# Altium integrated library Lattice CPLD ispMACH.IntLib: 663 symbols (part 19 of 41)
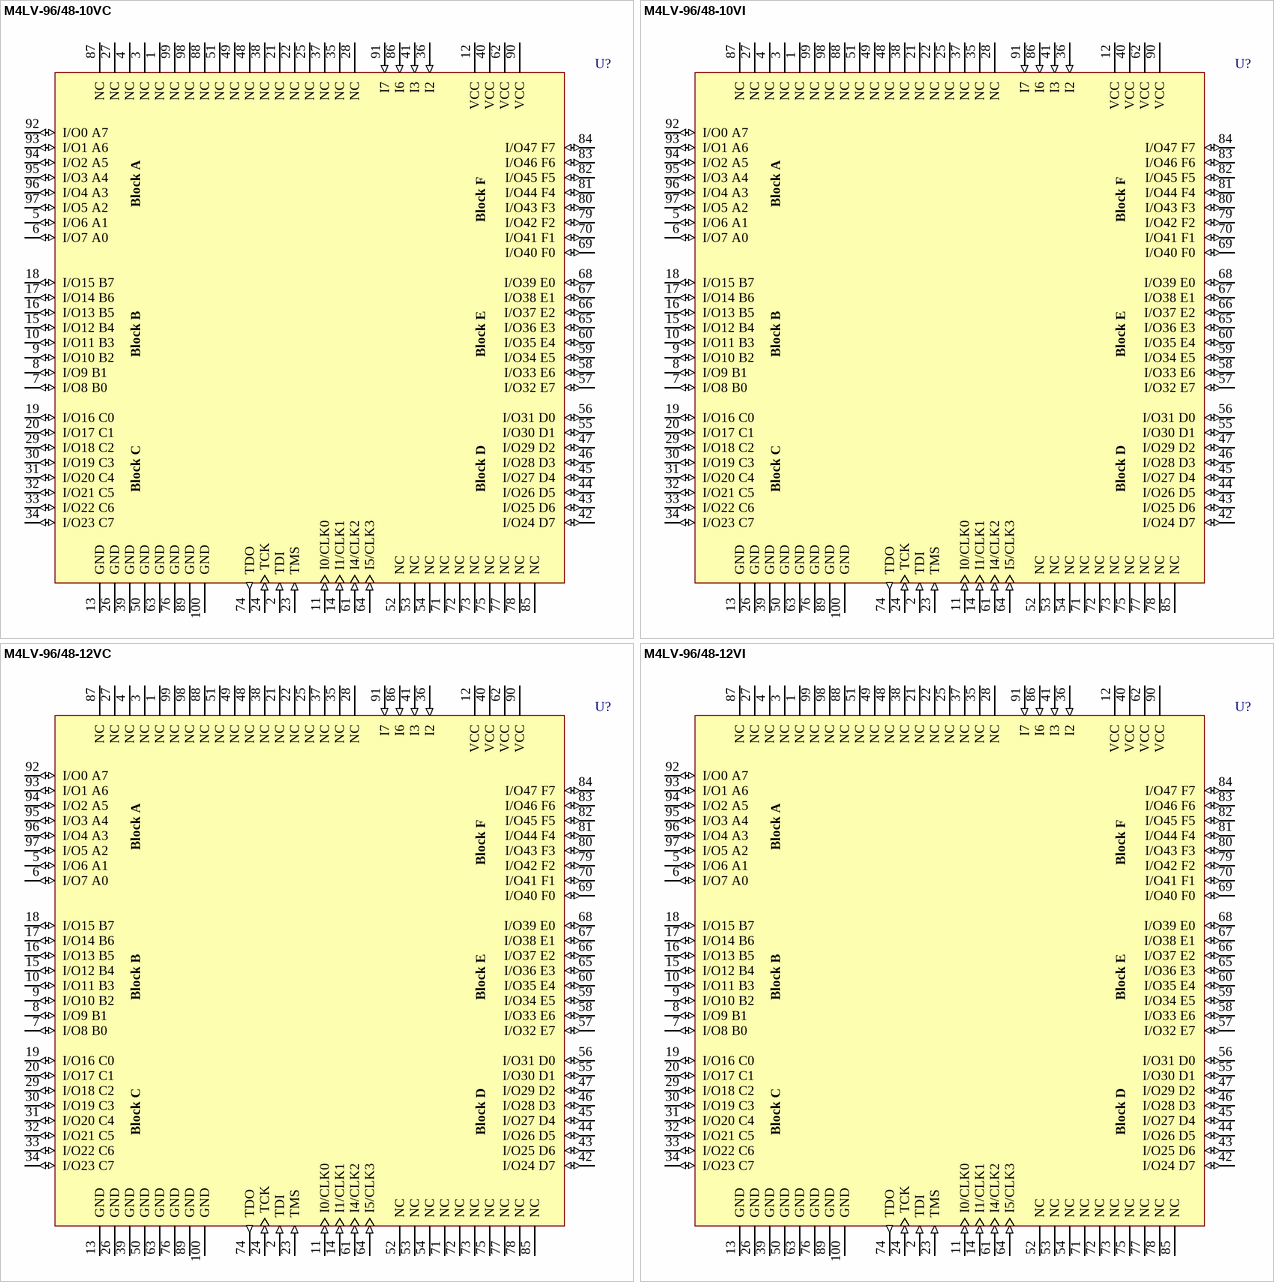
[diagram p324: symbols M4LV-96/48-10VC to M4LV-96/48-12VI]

## M4LV-96/48-10VI
designator U?
High-Performance EE CMOS In-System Programmable Logic
footprint TQFP100_N (Thin QFP, 100-Leads, Body 14x14mm, Pitch 0.5mm, IPC Medium Density)
footprint TQFP100_L (Thin QFP, 100-Leads, Body 14x14mm, Pitch 0.5mm, IPC High Density)
footprint TQFP100_M (Thin QFP, 100-Leads, Body 14x14mm, Pitch 0.5mm, IPC Low Density)
3D model M4LV-TQFP100 (100-Pin Thin Quad Flat Pack (TQFP100))
pins: 1 NC, 2 TDI (in), 3 NC, 4 NC, 5 I/O6 A1 (io), 6 I/O7 A0 (io), 7 I/O8 B0 (io), 8 I/O9 B1 (io), 9 I/O10 B2 (io), 10 I/O11 B3 (io), 11 I0/CLK0 (in), 12 VCC (power), 13 GND (power), 14 I1/CLK1 (in), 15 I/O12 B4 (io), 16 I/O13 B5 (io), 17 I/O14 B6 (io), 18 I/O15 B7 (io), 19 I/O16 C0 (io), 20 I/O17 C1 (io), 21 NC, 22 NC, 23 TMS (in), 24 TCK (in), 25 NC, 26 GND (power), 27 NC, 28 NC, 29 I/O18 C2 (io), 30 I/O19 C3 (io), 31 I/O20 C4 (io), 32 I/O21 C5 (io), 33 I/O22 C6 (io), 34 I/O23 C7 (io), 35 NC, 36 I2 (in), 37 NC, 38 NC, 39 GND (power), 40 VCC (power), 41 I3 (in), 42 I/O24 D7 (io), 43 I/O25 D6 (io), 44 I/O26 D5 (io), 45 I/O27 D4 (io), 46 I/O28 D3 (io), 47 I/O29 D2 (io), 48 NC, 49 NC, 50 GND (power), 51 NC, 52 NC, 53 NC, 54 NC, 55 I/O30 D1 (io), 56 I/O31 D0 (io), 57 I/O32 E7 (io), 58 I/O33 E6 (io), 59 I/O34 E5 (io), 60 I/O35 E4 (io), 61 I4/CLK2 (in), 62 VCC (power), 63 GND (power), 64 I5/CLK3 (in), 65 I/O36 E3 (io), 66 I/O37 E2 (io), 67 I/O38 E1 (io), 68 I/O39 E0 (io), 69 I/O40 F0 (io), 70 I/O41 F1 (io), 71 NC, 72 NC, 73 NC, 74 TDO (out), 75 NC, 76 GND (power), 77 NC, 78 NC, 79 I/O42 F2 (io), 80 I/O43 F3 (io), 81 I/O44 F4 (io), 82 I/O45 F5 (io), 83 I/O46 F6 (io), 84 I/O47 F7 (io), 85 NC, 86 I6 (in), 87 NC, 88 NC, 89 GND (power), 90 VCC (power), 91 I7 (in), 92 I/O0 A7 (io), 93 I/O1 A6 (io), 94 I/O2 A5 (io), 95 I/O3 A4 (io), 96 I/O4 A3 (io), 97 I/O5 A2 (io), 98 NC, 99 NC, 100 GND (power)

## M4LV-96/48-12VC
designator U?
High-Performance EE CMOS In-System Programmable Logic
footprint TQFP100_N (Thin QFP, 100-Leads, Body 14x14mm, Pitch 0.5mm, IPC Medium Density)
footprint TQFP100_L (Thin QFP, 100-Leads, Body 14x14mm, Pitch 0.5mm, IPC High Density)
footprint TQFP100_M (Thin QFP, 100-Leads, Body 14x14mm, Pitch 0.5mm, IPC Low Density)
3D model M4LV-TQFP100 (100-Pin Thin Quad Flat Pack (TQFP100))
pins: 1 NC, 2 TDI (in), 3 NC, 4 NC, 5 I/O6 A1 (io), 6 I/O7 A0 (io), 7 I/O8 B0 (io), 8 I/O9 B1 (io), 9 I/O10 B2 (io), 10 I/O11 B3 (io), 11 I0/CLK0 (in), 12 VCC (power), 13 GND (power), 14 I1/CLK1 (in), 15 I/O12 B4 (io), 16 I/O13 B5 (io), 17 I/O14 B6 (io), 18 I/O15 B7 (io), 19 I/O16 C0 (io), 20 I/O17 C1 (io), 21 NC, 22 NC, 23 TMS (in), 24 TCK (in), 25 NC, 26 GND (power), 27 NC, 28 NC, 29 I/O18 C2 (io), 30 I/O19 C3 (io), 31 I/O20 C4 (io), 32 I/O21 C5 (io), 33 I/O22 C6 (io), 34 I/O23 C7 (io), 35 NC, 36 I2 (in), 37 NC, 38 NC, 39 GND (power), 40 VCC (power), 41 I3 (in), 42 I/O24 D7 (io), 43 I/O25 D6 (io), 44 I/O26 D5 (io), 45 I/O27 D4 (io), 46 I/O28 D3 (io), 47 I/O29 D2 (io), 48 NC, 49 NC, 50 GND (power), 51 NC, 52 NC, 53 NC, 54 NC, 55 I/O30 D1 (io), 56 I/O31 D0 (io), 57 I/O32 E7 (io), 58 I/O33 E6 (io), 59 I/O34 E5 (io), 60 I/O35 E4 (io), 61 I4/CLK2 (in), 62 VCC (power), 63 GND (power), 64 I5/CLK3 (in), 65 I/O36 E3 (io), 66 I/O37 E2 (io), 67 I/O38 E1 (io), 68 I/O39 E0 (io), 69 I/O40 F0 (io), 70 I/O41 F1 (io), 71 NC, 72 NC, 73 NC, 74 TDO (out), 75 NC, 76 GND (power), 77 NC, 78 NC, 79 I/O42 F2 (io), 80 I/O43 F3 (io), 81 I/O44 F4 (io), 82 I/O45 F5 (io), 83 I/O46 F6 (io), 84 I/O47 F7 (io), 85 NC, 86 I6 (in), 87 NC, 88 NC, 89 GND (power), 90 VCC (power), 91 I7 (in), 92 I/O0 A7 (io), 93 I/O1 A6 (io), 94 I/O2 A5 (io), 95 I/O3 A4 (io), 96 I/O4 A3 (io), 97 I/O5 A2 (io), 98 NC, 99 NC, 100 GND (power)

## M4LV-96/48-12VI
designator U?
High-Performance EE CMOS In-System Programmable Logic
footprint TQFP100_N (Thin QFP, 100-Leads, Body 14x14mm, Pitch 0.5mm, IPC Medium Density)
footprint TQFP100_L (Thin QFP, 100-Leads, Body 14x14mm, Pitch 0.5mm, IPC High Density)
footprint TQFP100_M (Thin QFP, 100-Leads, Body 14x14mm, Pitch 0.5mm, IPC Low Density)
3D model M4LV-TQFP100 (100-Pin Thin Quad Flat Pack (TQFP100))
pins: 1 NC, 2 TDI (in), 3 NC, 4 NC, 5 I/O6 A1 (io), 6 I/O7 A0 (io), 7 I/O8 B0 (io), 8 I/O9 B1 (io), 9 I/O10 B2 (io), 10 I/O11 B3 (io), 11 I0/CLK0 (in), 12 VCC (power), 13 GND (power), 14 I1/CLK1 (in), 15 I/O12 B4 (io), 16 I/O13 B5 (io), 17 I/O14 B6 (io), 18 I/O15 B7 (io), 19 I/O16 C0 (io), 20 I/O17 C1 (io), 21 NC, 22 NC, 23 TMS (in), 24 TCK (in), 25 NC, 26 GND (power), 27 NC, 28 NC, 29 I/O18 C2 (io), 30 I/O19 C3 (io), 31 I/O20 C4 (io), 32 I/O21 C5 (io), 33 I/O22 C6 (io), 34 I/O23 C7 (io), 35 NC, 36 I2 (in), 37 NC, 38 NC, 39 GND (power), 40 VCC (power), 41 I3 (in), 42 I/O24 D7 (io), 43 I/O25 D6 (io), 44 I/O26 D5 (io), 45 I/O27 D4 (io), 46 I/O28 D3 (io), 47 I/O29 D2 (io), 48 NC, 49 NC, 50 GND (power), 51 NC, 52 NC, 53 NC, 54 NC, 55 I/O30 D1 (io), 56 I/O31 D0 (io), 57 I/O32 E7 (io), 58 I/O33 E6 (io), 59 I/O34 E5 (io), 60 I/O35 E4 (io), 61 I4/CLK2 (in), 62 VCC (power), 63 GND (power), 64 I5/CLK3 (in), 65 I/O36 E3 (io), 66 I/O37 E2 (io), 67 I/O38 E1 (io), 68 I/O39 E0 (io), 69 I/O40 F0 (io), 70 I/O41 F1 (io), 71 NC, 72 NC, 73 NC, 74 TDO (out), 75 NC, 76 GND (power), 77 NC, 78 NC, 79 I/O42 F2 (io), 80 I/O43 F3 (io), 81 I/O44 F4 (io), 82 I/O45 F5 (io), 83 I/O46 F6 (io), 84 I/O47 F7 (io), 85 NC, 86 I6 (in), 87 NC, 88 NC, 89 GND (power), 90 VCC (power), 91 I7 (in), 92 I/O0 A7 (io), 93 I/O1 A6 (io), 94 I/O2 A5 (io), 95 I/O3 A4 (io), 96 I/O4 A3 (io), 97 I/O5 A2 (io), 98 NC, 99 NC, 100 GND (power)

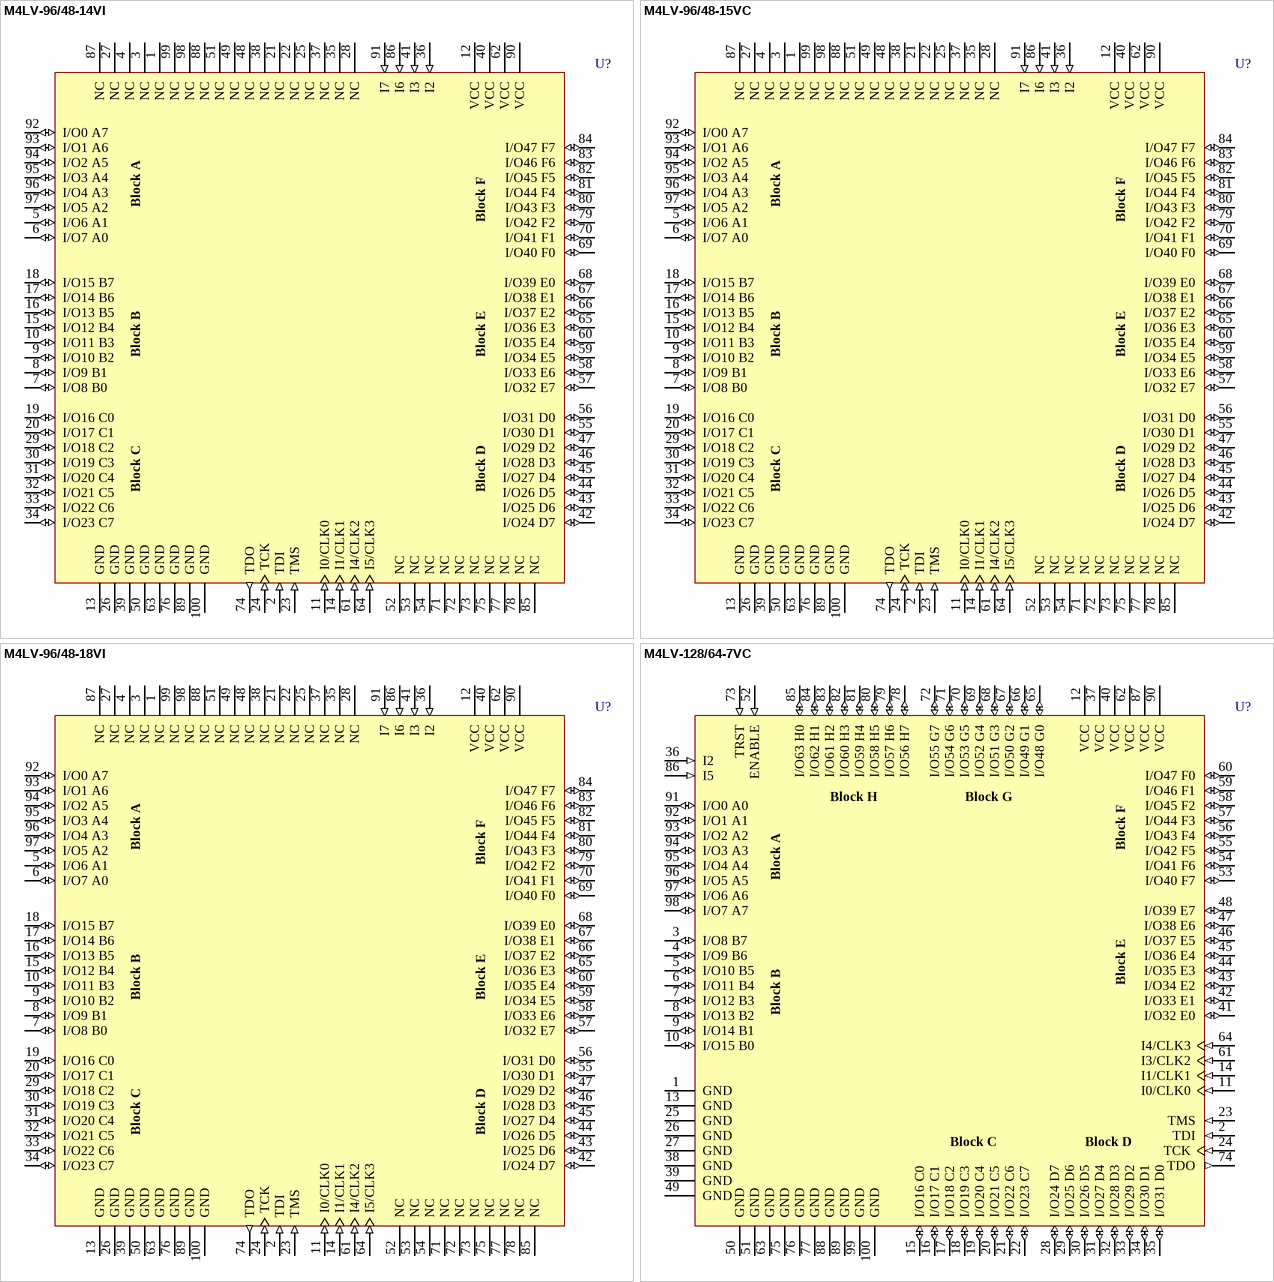
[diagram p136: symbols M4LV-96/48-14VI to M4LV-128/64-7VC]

## M4LV-96/48-14VI
designator U?
High-Performance EE CMOS In-System Programmable Logic
footprint TQFP100_N (Thin QFP, 100-Leads, Body 14x14mm, Pitch 0.5mm, IPC Medium Density)
footprint TQFP100_L (Thin QFP, 100-Leads, Body 14x14mm, Pitch 0.5mm, IPC High Density)
footprint TQFP100_M (Thin QFP, 100-Leads, Body 14x14mm, Pitch 0.5mm, IPC Low Density)
3D model M4LV-TQFP100 (100-Pin Thin Quad Flat Pack (TQFP100))
pins: 1 NC, 2 TDI (in), 3 NC, 4 NC, 5 I/O6 A1 (io), 6 I/O7 A0 (io), 7 I/O8 B0 (io), 8 I/O9 B1 (io), 9 I/O10 B2 (io), 10 I/O11 B3 (io), 11 I0/CLK0 (in), 12 VCC (power), 13 GND (power), 14 I1/CLK1 (in), 15 I/O12 B4 (io), 16 I/O13 B5 (io), 17 I/O14 B6 (io), 18 I/O15 B7 (io), 19 I/O16 C0 (io), 20 I/O17 C1 (io), 21 NC, 22 NC, 23 TMS (in), 24 TCK (in), 25 NC, 26 GND (power), 27 NC, 28 NC, 29 I/O18 C2 (io), 30 I/O19 C3 (io), 31 I/O20 C4 (io), 32 I/O21 C5 (io), 33 I/O22 C6 (io), 34 I/O23 C7 (io), 35 NC, 36 I2 (in), 37 NC, 38 NC, 39 GND (power), 40 VCC (power), 41 I3 (in), 42 I/O24 D7 (io), 43 I/O25 D6 (io), 44 I/O26 D5 (io), 45 I/O27 D4 (io), 46 I/O28 D3 (io), 47 I/O29 D2 (io), 48 NC, 49 NC, 50 GND (power), 51 NC, 52 NC, 53 NC, 54 NC, 55 I/O30 D1 (io), 56 I/O31 D0 (io), 57 I/O32 E7 (io), 58 I/O33 E6 (io), 59 I/O34 E5 (io), 60 I/O35 E4 (io), 61 I4/CLK2 (in), 62 VCC (power), 63 GND (power), 64 I5/CLK3 (in), 65 I/O36 E3 (io), 66 I/O37 E2 (io), 67 I/O38 E1 (io), 68 I/O39 E0 (io), 69 I/O40 F0 (io), 70 I/O41 F1 (io), 71 NC, 72 NC, 73 NC, 74 TDO (out), 75 NC, 76 GND (power), 77 NC, 78 NC, 79 I/O42 F2 (io), 80 I/O43 F3 (io), 81 I/O44 F4 (io), 82 I/O45 F5 (io), 83 I/O46 F6 (io), 84 I/O47 F7 (io), 85 NC, 86 I6 (in), 87 NC, 88 NC, 89 GND (power), 90 VCC (power), 91 I7 (in), 92 I/O0 A7 (io), 93 I/O1 A6 (io), 94 I/O2 A5 (io), 95 I/O3 A4 (io), 96 I/O4 A3 (io), 97 I/O5 A2 (io), 98 NC, 99 NC, 100 GND (power)

## M4LV-96/48-15VC
designator U?
High-Performance EE CMOS In-System Programmable Logic
footprint TQFP100_N (Thin QFP, 100-Leads, Body 14x14mm, Pitch 0.5mm, IPC Medium Density)
footprint TQFP100_L (Thin QFP, 100-Leads, Body 14x14mm, Pitch 0.5mm, IPC High Density)
footprint TQFP100_M (Thin QFP, 100-Leads, Body 14x14mm, Pitch 0.5mm, IPC Low Density)
3D model M4LV-TQFP100 (100-Pin Thin Quad Flat Pack (TQFP100))
pins: 1 NC, 2 TDI (in), 3 NC, 4 NC, 5 I/O6 A1 (io), 6 I/O7 A0 (io), 7 I/O8 B0 (io), 8 I/O9 B1 (io), 9 I/O10 B2 (io), 10 I/O11 B3 (io), 11 I0/CLK0 (in), 12 VCC (power), 13 GND (power), 14 I1/CLK1 (in), 15 I/O12 B4 (io), 16 I/O13 B5 (io), 17 I/O14 B6 (io), 18 I/O15 B7 (io), 19 I/O16 C0 (io), 20 I/O17 C1 (io), 21 NC, 22 NC, 23 TMS (in), 24 TCK (in), 25 NC, 26 GND (power), 27 NC, 28 NC, 29 I/O18 C2 (io), 30 I/O19 C3 (io), 31 I/O20 C4 (io), 32 I/O21 C5 (io), 33 I/O22 C6 (io), 34 I/O23 C7 (io), 35 NC, 36 I2 (in), 37 NC, 38 NC, 39 GND (power), 40 VCC (power), 41 I3 (in), 42 I/O24 D7 (io), 43 I/O25 D6 (io), 44 I/O26 D5 (io), 45 I/O27 D4 (io), 46 I/O28 D3 (io), 47 I/O29 D2 (io), 48 NC, 49 NC, 50 GND (power), 51 NC, 52 NC, 53 NC, 54 NC, 55 I/O30 D1 (io), 56 I/O31 D0 (io), 57 I/O32 E7 (io), 58 I/O33 E6 (io), 59 I/O34 E5 (io), 60 I/O35 E4 (io), 61 I4/CLK2 (in), 62 VCC (power), 63 GND (power), 64 I5/CLK3 (in), 65 I/O36 E3 (io), 66 I/O37 E2 (io), 67 I/O38 E1 (io), 68 I/O39 E0 (io), 69 I/O40 F0 (io), 70 I/O41 F1 (io), 71 NC, 72 NC, 73 NC, 74 TDO (out), 75 NC, 76 GND (power), 77 NC, 78 NC, 79 I/O42 F2 (io), 80 I/O43 F3 (io), 81 I/O44 F4 (io), 82 I/O45 F5 (io), 83 I/O46 F6 (io), 84 I/O47 F7 (io), 85 NC, 86 I6 (in), 87 NC, 88 NC, 89 GND (power), 90 VCC (power), 91 I7 (in), 92 I/O0 A7 (io), 93 I/O1 A6 (io), 94 I/O2 A5 (io), 95 I/O3 A4 (io), 96 I/O4 A3 (io), 97 I/O5 A2 (io), 98 NC, 99 NC, 100 GND (power)

## M4LV-96/48-18VI
designator U?
High-Performance EE CMOS In-System Programmable Logic
footprint TQFP100_N (Thin QFP, 100-Leads, Body 14x14mm, Pitch 0.5mm, IPC Medium Density)
footprint TQFP100_L (Thin QFP, 100-Leads, Body 14x14mm, Pitch 0.5mm, IPC High Density)
footprint TQFP100_M (Thin QFP, 100-Leads, Body 14x14mm, Pitch 0.5mm, IPC Low Density)
3D model M4LV-TQFP100 (100-Pin Thin Quad Flat Pack (TQFP100))
pins: 1 NC, 2 TDI (in), 3 NC, 4 NC, 5 I/O6 A1 (io), 6 I/O7 A0 (io), 7 I/O8 B0 (io), 8 I/O9 B1 (io), 9 I/O10 B2 (io), 10 I/O11 B3 (io), 11 I0/CLK0 (in), 12 VCC (power), 13 GND (power), 14 I1/CLK1 (in), 15 I/O12 B4 (io), 16 I/O13 B5 (io), 17 I/O14 B6 (io), 18 I/O15 B7 (io), 19 I/O16 C0 (io), 20 I/O17 C1 (io), 21 NC, 22 NC, 23 TMS (in), 24 TCK (in), 25 NC, 26 GND (power), 27 NC, 28 NC, 29 I/O18 C2 (io), 30 I/O19 C3 (io), 31 I/O20 C4 (io), 32 I/O21 C5 (io), 33 I/O22 C6 (io), 34 I/O23 C7 (io), 35 NC, 36 I2 (in), 37 NC, 38 NC, 39 GND (power), 40 VCC (power), 41 I3 (in), 42 I/O24 D7 (io), 43 I/O25 D6 (io), 44 I/O26 D5 (io), 45 I/O27 D4 (io), 46 I/O28 D3 (io), 47 I/O29 D2 (io), 48 NC, 49 NC, 50 GND (power), 51 NC, 52 NC, 53 NC, 54 NC, 55 I/O30 D1 (io), 56 I/O31 D0 (io), 57 I/O32 E7 (io), 58 I/O33 E6 (io), 59 I/O34 E5 (io), 60 I/O35 E4 (io), 61 I4/CLK2 (in), 62 VCC (power), 63 GND (power), 64 I5/CLK3 (in), 65 I/O36 E3 (io), 66 I/O37 E2 (io), 67 I/O38 E1 (io), 68 I/O39 E0 (io), 69 I/O40 F0 (io), 70 I/O41 F1 (io), 71 NC, 72 NC, 73 NC, 74 TDO (out), 75 NC, 76 GND (power), 77 NC, 78 NC, 79 I/O42 F2 (io), 80 I/O43 F3 (io), 81 I/O44 F4 (io), 82 I/O45 F5 (io), 83 I/O46 F6 (io), 84 I/O47 F7 (io), 85 NC, 86 I6 (in), 87 NC, 88 NC, 89 GND (power), 90 VCC (power), 91 I7 (in), 92 I/O0 A7 (io), 93 I/O1 A6 (io), 94 I/O2 A5 (io), 95 I/O3 A4 (io), 96 I/O4 A3 (io), 97 I/O5 A2 (io), 98 NC, 99 NC, 100 GND (power)

## M4LV-128/64-7VC
designator U?
High-Performance EE CMOS In-System Programmable Logic
footprint TQFP100_N (Thin QFP, 100-Leads, Body 14x14mm, Pitch 0.5mm, IPC Medium Density)
footprint TQFP100_L (Thin QFP, 100-Leads, Body 14x14mm, Pitch 0.5mm, IPC High Density)
footprint TQFP100_M (Thin QFP, 100-Leads, Body 14x14mm, Pitch 0.5mm, IPC Low Density)
3D model M4LV-TQFP100 (100-Pin Thin Quad Flat Pack (TQFP100))
pins: 1 GND (power), 2 TDI (in), 3 I/O8 B7 (io), 4 I/O9 B6 (io), 5 I/O10 B5 (io), 6 I/O11 B4 (io), 7 I/O12 B3 (io), 8 I/O13 B2 (io), 9 I/O14 B1 (io), 10 I/O15 B0 (io), 11 I0/CLK0 (in), 12 VCC (power), 13 GND (power), 14 I1/CLK1 (in), 15 I/O16 C0 (io), 16 I/O17 C1 (io), 17 I/O18 C2 (io), 18 I/O19 C3 (io), 19 I/O20 C4 (io), 20 I/O21 C5 (io), 21 I/O22 C6 (io), 22 I/O23 C7 (io), 23 TMS (in), 24 TCK (in), 25 GND (power), 26 GND (power), 27 GND (power), 28 I/O24 D7 (io), 29 I/O25 D6 (io), 30 I/O26 D5 (io), 31 I/O27 D4 (io), 32 I/O28 D3 (io), 33 I/O29 D2 (io), 34 I/O30 D1 (io), 35 I/O31 D0 (io), 36 I2 (in), 37 VCC (power), 38 GND (power), 39 GND (power), 40 VCC (power), 41 I/O32 E0 (io), 42 I/O33 E1 (io), 43 I/O34 E2 (io), 44 I/O35 E3 (io), 45 I/O36 E4 (io), 46 I/O37 E5 (io), 47 I/O38 E6 (io), 48 I/O39 E7 (io), 49 GND (power), 50 GND (power), 51 GND (power), 52 ENABLE (in), 53 I/O40 F7 (io), 54 I/O41 F6 (io), 55 I/O42 F5 (io), 56 I/O43 F4 (io), 57 I/O44 F3 (io), 58 I/O45 F2 (io), 59 I/O46 F1 (io), 60 I/O47 F0 (io), 61 I3/CLK2 (in), 62 VCC (power), 63 GND (power), 64 I4/CLK3 (in), 65 I/O48 G0 (io), 66 I/O49 G1 (io), 67 I/O50 G2 (io), 68 I/O51 G3 (io), 69 I/O52 G4 (io), 70 I/O53 G5 (io), 71 I/O54 G6 (io), 72 I/O55 G7 (io), 73 TRST (in), 74 TDO (out), 75 GND (power), 76 GND (power), 77 GND (power), 78 I/O56 H7 (io), 79 I/O57 H6 (io), 80 I/O58 H5 (io), 81 I/O59 H4 (io), 82 I/O60 H3 (io), 83 I/O61 H2 (io), 84 I/O62 H1 (io), 85 I/O63 H0 (io), 86 I5 (in), 87 VCC (power), 88 GND (power), 89 GND (power), 90 VCC (power), 91 I/O0 A0 (io), 92 I/O1 A1 (io), 93 I/O2 A2 (io), 94 I/O3 A3 (io), 95 I/O4 A4 (io), 96 I/O5 A5 (io), 97 I/O6 A6 (io), 98 I/O7 A7 (io), 99 GND (power), 100 GND (power)

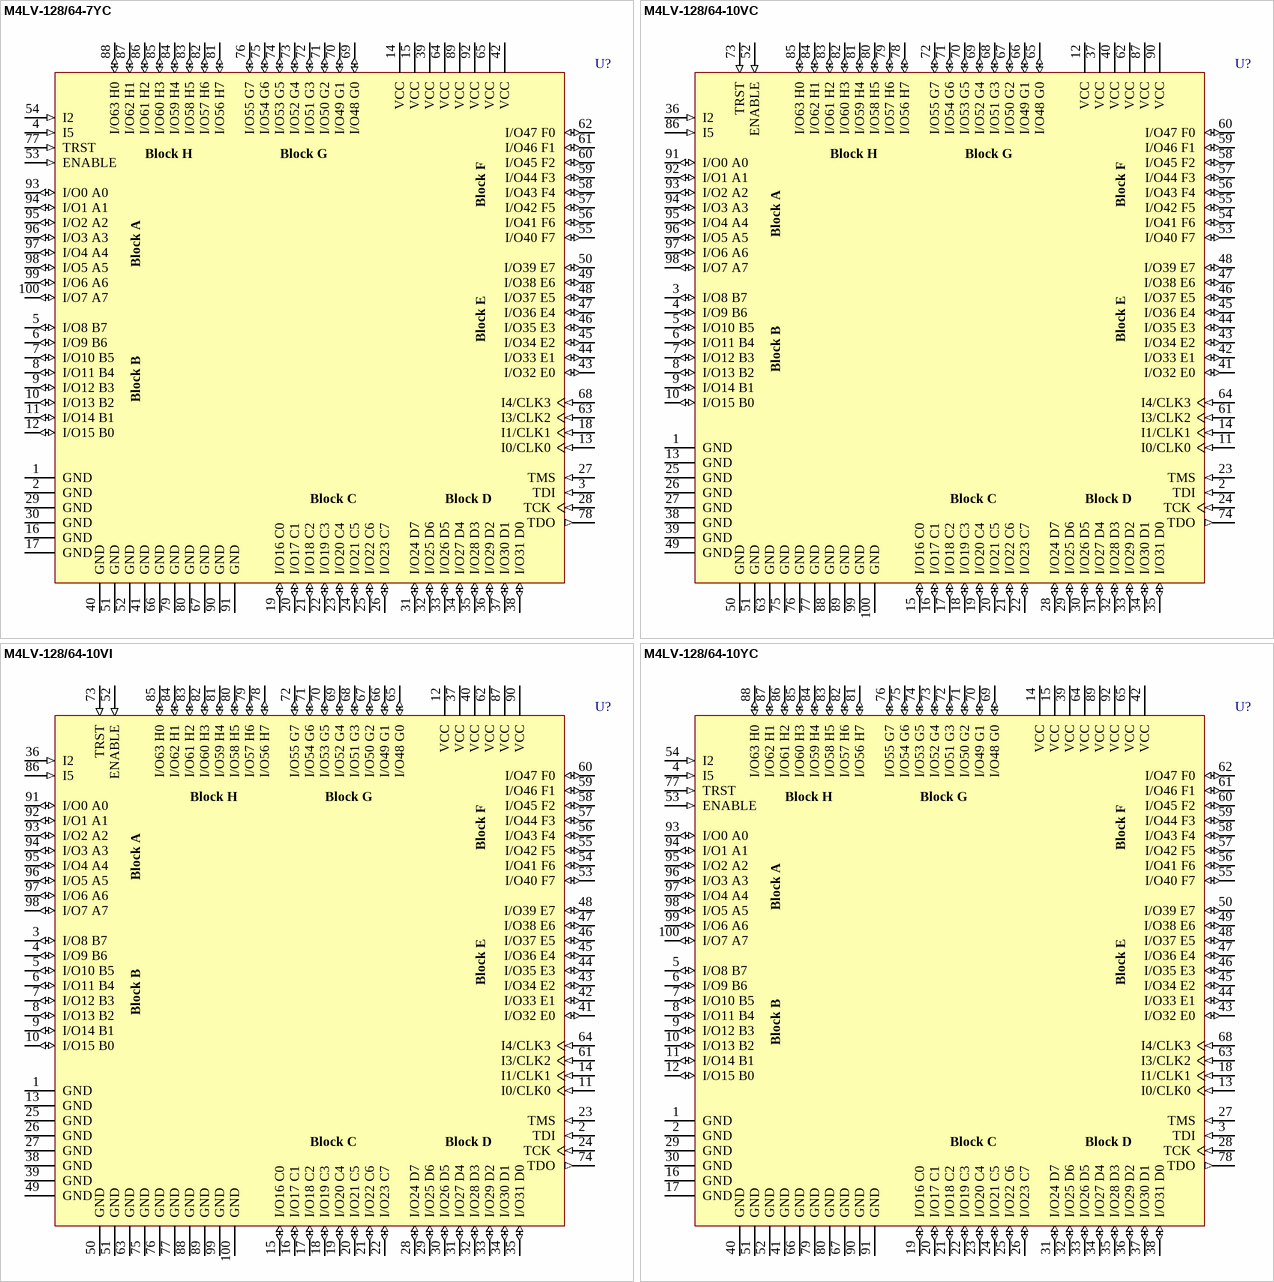
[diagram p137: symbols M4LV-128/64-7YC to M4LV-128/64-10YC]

## M4LV-128/64-7YC
designator U?
High-Performance EE CMOS In-System Programmable Logic
footprint PQFP100_N (QFP, 100-Leads, Body 20x14mm, Pitch 0.65mm, IPC Medium Density)
footprint PQFP100_L (QFP, 100-Leads, Body 20x14mm, Pitch 0.65mm, IPC High Density)
footprint PQFP100_M (QFP, 100-Leads, Body 20x14mm, Pitch 0.65mm, IPC Low Density)
3D model PQFP-100 (100-Pin Quad Flat Pack Rectangular 0.65 mm Pitch)
pins: 1 GND (power), 2 GND (power), 3 TDI (in), 4 I5 (in), 5 I/O8 B7 (io), 6 I/O9 B6 (io), 7 I/O10 B5 (io), 8 I/O11 B4 (io), 9 I/O12 B3 (io), 10 I/O13 B2 (io), 11 I/O14 B1 (io), 12 I/O15 B0 (io), 13 I0/CLK0 (in), 14 VCC (power), 15 VCC (power), 16 GND (power), 17 GND (power), 18 I1/CLK1 (in), 19 I/O16 C0 (io), 20 I/O17 C1 (io), 21 I/O18 C2 (io), 22 I/O19 C3 (io), 23 I/O20 C4 (io), 24 I/O21 C5 (io), 25 I/O22 C6 (io), 26 I/O23 C7 (io), 27 TMS (in), 28 TCK (in), 29 GND (power), 30 GND (power), 31 I/O24 D7 (io), 32 I/O25 D6 (io), 33 I/O26 D5 (io), 34 I/O27 D4 (io), 35 I/O28 D3 (io), 36 I/O29 D2 (io), 37 I/O30 D1 (io), 38 I/O31 D0 (io), 39 VCC (power), 40 GND (power), 41 GND (power), 42 VCC (power), 43 I/O32 E0 (io), 44 I/O33 E1 (io), 45 I/O34 E2 (io), 46 I/O35 E3 (io), 47 I/O36 E4 (io), 48 I/O37 E5 (io), 49 I/O38 E6 (io), 50 I/O39 E7 (io), 51 GND (power), 52 GND (power), 53 ENABLE (in), 54 I2 (in), 55 I/O40 F7 (io), 56 I/O41 F6 (io), 57 I/O42 F5 (io), 58 I/O43 F4 (io), 59 I/O44 F3 (io), 60 I/O45 F2 (io), 61 I/O46 F1 (io), 62 I/O47 F0 (io), 63 I3/CLK2 (in), 64 VCC (power), 65 VCC (power), 66 GND (power), 67 GND (power), 68 I4/CLK3 (in), 69 I/O48 G0 (io), 70 I/O49 G1 (io), 71 I/O50 G2 (io), 72 I/O51 G3 (io), 73 I/O52 G4 (io), 74 I/O53 G5 (io), 75 I/O54 G6 (io), 76 I/O55 G7 (io), 77 TRST (in), 78 TDO (out), 79 GND (power), 80 GND (power), 81 I/O56 H7 (io), 82 I/O57 H6 (io), 83 I/O58 H5 (io), 84 I/O59 H4 (io), 85 I/O60 H3 (io), 86 I/O61 H2 (io), 87 I/O62 H1 (io), 88 I/O63 H0 (io), 89 VCC (power), 90 GND (power), 91 GND (power), 92 VCC (power), 93 I/O0 A0 (io), 94 I/O1 A1 (io), 95 I/O2 A2 (io), 96 I/O3 A3 (io), 97 I/O4 A4 (io), 98 I/O5 A5 (io), 99 I/O6 A6 (io), 100 I/O7 A7 (io)

## M4LV-128/64-10VC
designator U?
High-Performance EE CMOS In-System Programmable Logic
footprint TQFP100_N (Thin QFP, 100-Leads, Body 14x14mm, Pitch 0.5mm, IPC Medium Density)
footprint TQFP100_L (Thin QFP, 100-Leads, Body 14x14mm, Pitch 0.5mm, IPC High Density)
footprint TQFP100_M (Thin QFP, 100-Leads, Body 14x14mm, Pitch 0.5mm, IPC Low Density)
3D model M4LV-TQFP100 (100-Pin Thin Quad Flat Pack (TQFP100))
pins: 1 GND (power), 2 TDI (in), 3 I/O8 B7 (io), 4 I/O9 B6 (io), 5 I/O10 B5 (io), 6 I/O11 B4 (io), 7 I/O12 B3 (io), 8 I/O13 B2 (io), 9 I/O14 B1 (io), 10 I/O15 B0 (io), 11 I0/CLK0 (in), 12 VCC (power), 13 GND (power), 14 I1/CLK1 (in), 15 I/O16 C0 (io), 16 I/O17 C1 (io), 17 I/O18 C2 (io), 18 I/O19 C3 (io), 19 I/O20 C4 (io), 20 I/O21 C5 (io), 21 I/O22 C6 (io), 22 I/O23 C7 (io), 23 TMS (in), 24 TCK (in), 25 GND (power), 26 GND (power), 27 GND (power), 28 I/O24 D7 (io), 29 I/O25 D6 (io), 30 I/O26 D5 (io), 31 I/O27 D4 (io), 32 I/O28 D3 (io), 33 I/O29 D2 (io), 34 I/O30 D1 (io), 35 I/O31 D0 (io), 36 I2 (in), 37 VCC (power), 38 GND (power), 39 GND (power), 40 VCC (power), 41 I/O32 E0 (io), 42 I/O33 E1 (io), 43 I/O34 E2 (io), 44 I/O35 E3 (io), 45 I/O36 E4 (io), 46 I/O37 E5 (io), 47 I/O38 E6 (io), 48 I/O39 E7 (io), 49 GND (power), 50 GND (power), 51 GND (power), 52 ENABLE (in), 53 I/O40 F7 (io), 54 I/O41 F6 (io), 55 I/O42 F5 (io), 56 I/O43 F4 (io), 57 I/O44 F3 (io), 58 I/O45 F2 (io), 59 I/O46 F1 (io), 60 I/O47 F0 (io), 61 I3/CLK2 (in), 62 VCC (power), 63 GND (power), 64 I4/CLK3 (in), 65 I/O48 G0 (io), 66 I/O49 G1 (io), 67 I/O50 G2 (io), 68 I/O51 G3 (io), 69 I/O52 G4 (io), 70 I/O53 G5 (io), 71 I/O54 G6 (io), 72 I/O55 G7 (io), 73 TRST (in), 74 TDO (out), 75 GND (power), 76 GND (power), 77 GND (power), 78 I/O56 H7 (io), 79 I/O57 H6 (io), 80 I/O58 H5 (io), 81 I/O59 H4 (io), 82 I/O60 H3 (io), 83 I/O61 H2 (io), 84 I/O62 H1 (io), 85 I/O63 H0 (io), 86 I5 (in), 87 VCC (power), 88 GND (power), 89 GND (power), 90 VCC (power), 91 I/O0 A0 (io), 92 I/O1 A1 (io), 93 I/O2 A2 (io), 94 I/O3 A3 (io), 95 I/O4 A4 (io), 96 I/O5 A5 (io), 97 I/O6 A6 (io), 98 I/O7 A7 (io), 99 GND (power), 100 GND (power)

## M4LV-128/64-10VI
designator U?
High-Performance EE CMOS In-System Programmable Logic
footprint TQFP100_N (Thin QFP, 100-Leads, Body 14x14mm, Pitch 0.5mm, IPC Medium Density)
footprint TQFP100_L (Thin QFP, 100-Leads, Body 14x14mm, Pitch 0.5mm, IPC High Density)
footprint TQFP100_M (Thin QFP, 100-Leads, Body 14x14mm, Pitch 0.5mm, IPC Low Density)
3D model M4LV-TQFP100 (100-Pin Thin Quad Flat Pack (TQFP100))
pins: 1 GND (power), 2 TDI (in), 3 I/O8 B7 (io), 4 I/O9 B6 (io), 5 I/O10 B5 (io), 6 I/O11 B4 (io), 7 I/O12 B3 (io), 8 I/O13 B2 (io), 9 I/O14 B1 (io), 10 I/O15 B0 (io), 11 I0/CLK0 (in), 12 VCC (power), 13 GND (power), 14 I1/CLK1 (in), 15 I/O16 C0 (io), 16 I/O17 C1 (io), 17 I/O18 C2 (io), 18 I/O19 C3 (io), 19 I/O20 C4 (io), 20 I/O21 C5 (io), 21 I/O22 C6 (io), 22 I/O23 C7 (io), 23 TMS (in), 24 TCK (in), 25 GND (power), 26 GND (power), 27 GND (power), 28 I/O24 D7 (io), 29 I/O25 D6 (io), 30 I/O26 D5 (io), 31 I/O27 D4 (io), 32 I/O28 D3 (io), 33 I/O29 D2 (io), 34 I/O30 D1 (io), 35 I/O31 D0 (io), 36 I2 (in), 37 VCC (power), 38 GND (power), 39 GND (power), 40 VCC (power), 41 I/O32 E0 (io), 42 I/O33 E1 (io), 43 I/O34 E2 (io), 44 I/O35 E3 (io), 45 I/O36 E4 (io), 46 I/O37 E5 (io), 47 I/O38 E6 (io), 48 I/O39 E7 (io), 49 GND (power), 50 GND (power), 51 GND (power), 52 ENABLE (in), 53 I/O40 F7 (io), 54 I/O41 F6 (io), 55 I/O42 F5 (io), 56 I/O43 F4 (io), 57 I/O44 F3 (io), 58 I/O45 F2 (io), 59 I/O46 F1 (io), 60 I/O47 F0 (io), 61 I3/CLK2 (in), 62 VCC (power), 63 GND (power), 64 I4/CLK3 (in), 65 I/O48 G0 (io), 66 I/O49 G1 (io), 67 I/O50 G2 (io), 68 I/O51 G3 (io), 69 I/O52 G4 (io), 70 I/O53 G5 (io), 71 I/O54 G6 (io), 72 I/O55 G7 (io), 73 TRST (in), 74 TDO (out), 75 GND (power), 76 GND (power), 77 GND (power), 78 I/O56 H7 (io), 79 I/O57 H6 (io), 80 I/O58 H5 (io), 81 I/O59 H4 (io), 82 I/O60 H3 (io), 83 I/O61 H2 (io), 84 I/O62 H1 (io), 85 I/O63 H0 (io), 86 I5 (in), 87 VCC (power), 88 GND (power), 89 GND (power), 90 VCC (power), 91 I/O0 A0 (io), 92 I/O1 A1 (io), 93 I/O2 A2 (io), 94 I/O3 A3 (io), 95 I/O4 A4 (io), 96 I/O5 A5 (io), 97 I/O6 A6 (io), 98 I/O7 A7 (io), 99 GND (power), 100 GND (power)

## M4LV-128/64-10YC
designator U?
High-Performance EE CMOS In-System Programmable Logic
footprint PQFP100_N (QFP, 100-Leads, Body 20x14mm, Pitch 0.65mm, IPC Medium Density)
footprint PQFP100_L (QFP, 100-Leads, Body 20x14mm, Pitch 0.65mm, IPC High Density)
footprint PQFP100_M (QFP, 100-Leads, Body 20x14mm, Pitch 0.65mm, IPC Low Density)
3D model PQFP-100 (100-Pin Quad Flat Pack Rectangular 0.65 mm Pitch)
pins: 1 GND (power), 2 GND (power), 3 TDI (in), 4 I5 (in), 5 I/O8 B7 (io), 6 I/O9 B6 (io), 7 I/O10 B5 (io), 8 I/O11 B4 (io), 9 I/O12 B3 (io), 10 I/O13 B2 (io), 11 I/O14 B1 (io), 12 I/O15 B0 (io), 13 I0/CLK0 (in), 14 VCC (power), 15 VCC (power), 16 GND (power), 17 GND (power), 18 I1/CLK1 (in), 19 I/O16 C0 (io), 20 I/O17 C1 (io), 21 I/O18 C2 (io), 22 I/O19 C3 (io), 23 I/O20 C4 (io), 24 I/O21 C5 (io), 25 I/O22 C6 (io), 26 I/O23 C7 (io), 27 TMS (in), 28 TCK (in), 29 GND (power), 30 GND (power), 31 I/O24 D7 (io), 32 I/O25 D6 (io), 33 I/O26 D5 (io), 34 I/O27 D4 (io), 35 I/O28 D3 (io), 36 I/O29 D2 (io), 37 I/O30 D1 (io), 38 I/O31 D0 (io), 39 VCC (power), 40 GND (power), 41 GND (power), 42 VCC (power), 43 I/O32 E0 (io), 44 I/O33 E1 (io), 45 I/O34 E2 (io), 46 I/O35 E3 (io), 47 I/O36 E4 (io), 48 I/O37 E5 (io), 49 I/O38 E6 (io), 50 I/O39 E7 (io), 51 GND (power), 52 GND (power), 53 ENABLE (in), 54 I2 (in), 55 I/O40 F7 (io), 56 I/O41 F6 (io), 57 I/O42 F5 (io), 58 I/O43 F4 (io), 59 I/O44 F3 (io), 60 I/O45 F2 (io), 61 I/O46 F1 (io), 62 I/O47 F0 (io), 63 I3/CLK2 (in), 64 VCC (power), 65 VCC (power), 66 GND (power), 67 GND (power), 68 I4/CLK3 (in), 69 I/O48 G0 (io), 70 I/O49 G1 (io), 71 I/O50 G2 (io), 72 I/O51 G3 (io), 73 I/O52 G4 (io), 74 I/O53 G5 (io), 75 I/O54 G6 (io), 76 I/O55 G7 (io), 77 TRST (in), 78 TDO (out), 79 GND (power), 80 GND (power), 81 I/O56 H7 (io), 82 I/O57 H6 (io), 83 I/O58 H5 (io), 84 I/O59 H4 (io), 85 I/O60 H3 (io), 86 I/O61 H2 (io), 87 I/O62 H1 (io), 88 I/O63 H0 (io), 89 VCC (power), 90 GND (power), 91 GND (power), 92 VCC (power), 93 I/O0 A0 (io), 94 I/O1 A1 (io), 95 I/O2 A2 (io), 96 I/O3 A3 (io), 97 I/O4 A4 (io), 98 I/O5 A5 (io), 99 I/O6 A6 (io), 100 I/O7 A7 (io)

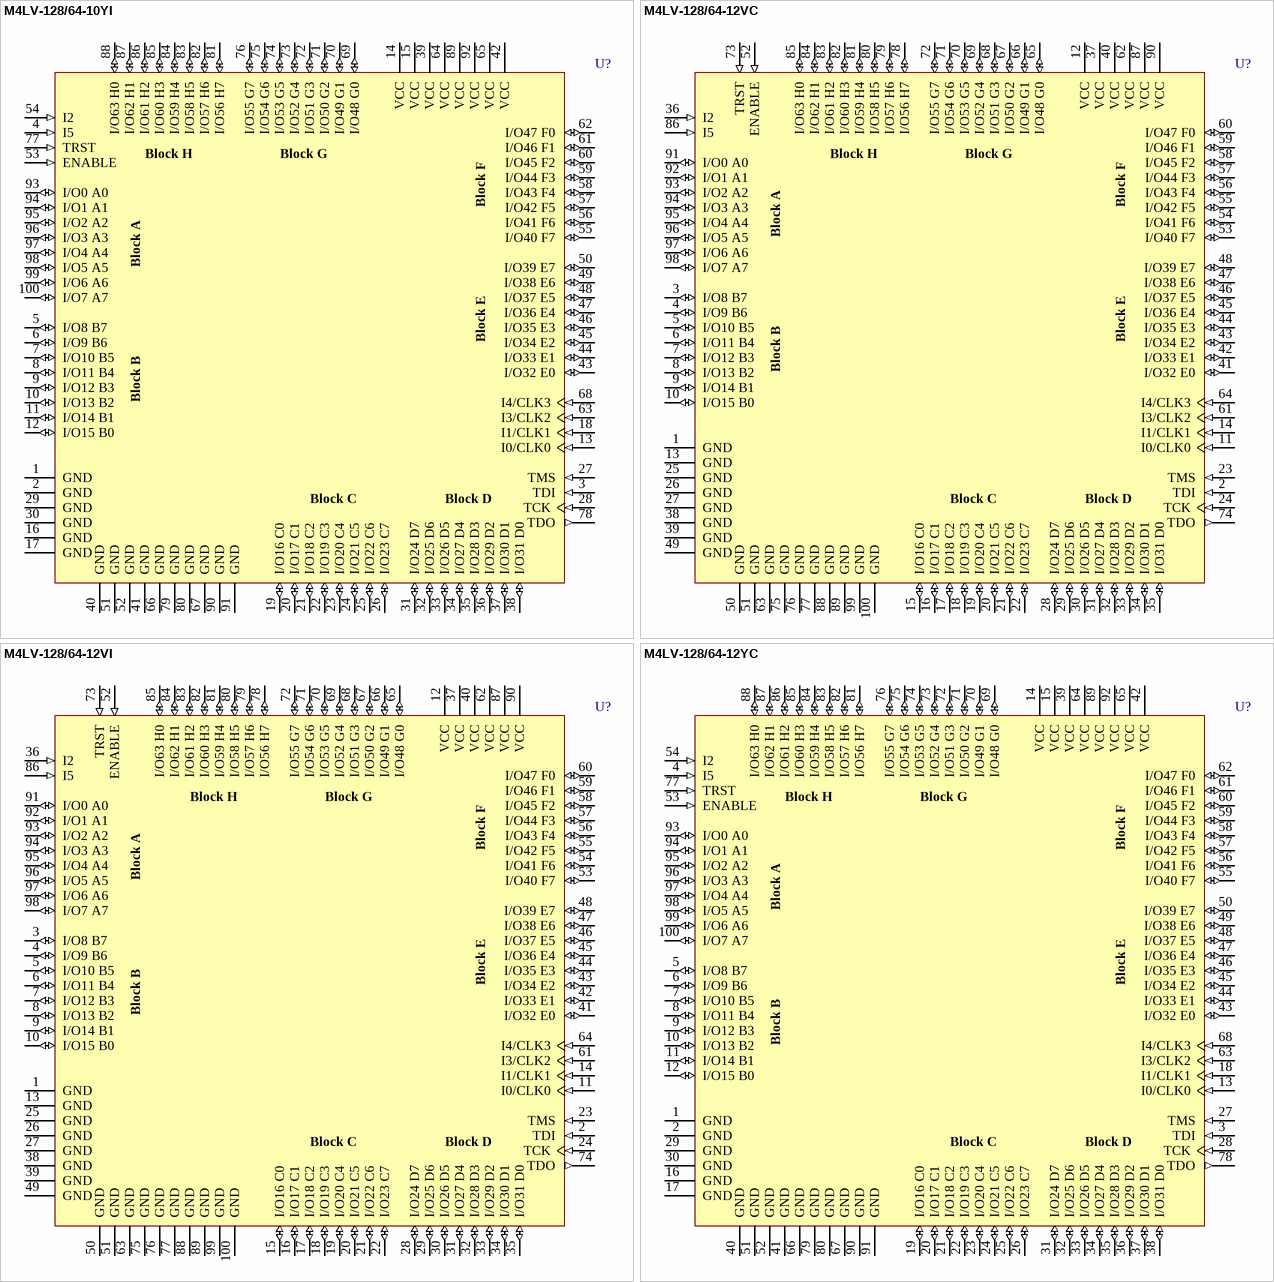
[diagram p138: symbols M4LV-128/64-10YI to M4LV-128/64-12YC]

## M4LV-128/64-10YI
designator U?
High-Performance EE CMOS In-System Programmable Logic
footprint PQFP100_N (QFP, 100-Leads, Body 20x14mm, Pitch 0.65mm, IPC Medium Density)
footprint PQFP100_L (QFP, 100-Leads, Body 20x14mm, Pitch 0.65mm, IPC High Density)
footprint PQFP100_M (QFP, 100-Leads, Body 20x14mm, Pitch 0.65mm, IPC Low Density)
3D model PQFP-100 (100-Pin Quad Flat Pack Rectangular 0.65 mm Pitch)
pins: 1 GND (power), 2 GND (power), 3 TDI (in), 4 I5 (in), 5 I/O8 B7 (io), 6 I/O9 B6 (io), 7 I/O10 B5 (io), 8 I/O11 B4 (io), 9 I/O12 B3 (io), 10 I/O13 B2 (io), 11 I/O14 B1 (io), 12 I/O15 B0 (io), 13 I0/CLK0 (in), 14 VCC (power), 15 VCC (power), 16 GND (power), 17 GND (power), 18 I1/CLK1 (in), 19 I/O16 C0 (io), 20 I/O17 C1 (io), 21 I/O18 C2 (io), 22 I/O19 C3 (io), 23 I/O20 C4 (io), 24 I/O21 C5 (io), 25 I/O22 C6 (io), 26 I/O23 C7 (io), 27 TMS (in), 28 TCK (in), 29 GND (power), 30 GND (power), 31 I/O24 D7 (io), 32 I/O25 D6 (io), 33 I/O26 D5 (io), 34 I/O27 D4 (io), 35 I/O28 D3 (io), 36 I/O29 D2 (io), 37 I/O30 D1 (io), 38 I/O31 D0 (io), 39 VCC (power), 40 GND (power), 41 GND (power), 42 VCC (power), 43 I/O32 E0 (io), 44 I/O33 E1 (io), 45 I/O34 E2 (io), 46 I/O35 E3 (io), 47 I/O36 E4 (io), 48 I/O37 E5 (io), 49 I/O38 E6 (io), 50 I/O39 E7 (io), 51 GND (power), 52 GND (power), 53 ENABLE (in), 54 I2 (in), 55 I/O40 F7 (io), 56 I/O41 F6 (io), 57 I/O42 F5 (io), 58 I/O43 F4 (io), 59 I/O44 F3 (io), 60 I/O45 F2 (io), 61 I/O46 F1 (io), 62 I/O47 F0 (io), 63 I3/CLK2 (in), 64 VCC (power), 65 VCC (power), 66 GND (power), 67 GND (power), 68 I4/CLK3 (in), 69 I/O48 G0 (io), 70 I/O49 G1 (io), 71 I/O50 G2 (io), 72 I/O51 G3 (io), 73 I/O52 G4 (io), 74 I/O53 G5 (io), 75 I/O54 G6 (io), 76 I/O55 G7 (io), 77 TRST (in), 78 TDO (out), 79 GND (power), 80 GND (power), 81 I/O56 H7 (io), 82 I/O57 H6 (io), 83 I/O58 H5 (io), 84 I/O59 H4 (io), 85 I/O60 H3 (io), 86 I/O61 H2 (io), 87 I/O62 H1 (io), 88 I/O63 H0 (io), 89 VCC (power), 90 GND (power), 91 GND (power), 92 VCC (power), 93 I/O0 A0 (io), 94 I/O1 A1 (io), 95 I/O2 A2 (io), 96 I/O3 A3 (io), 97 I/O4 A4 (io), 98 I/O5 A5 (io), 99 I/O6 A6 (io), 100 I/O7 A7 (io)

## M4LV-128/64-12VC
designator U?
High-Performance EE CMOS In-System Programmable Logic
footprint TQFP100_N (Thin QFP, 100-Leads, Body 14x14mm, Pitch 0.5mm, IPC Medium Density)
footprint TQFP100_L (Thin QFP, 100-Leads, Body 14x14mm, Pitch 0.5mm, IPC High Density)
footprint TQFP100_M (Thin QFP, 100-Leads, Body 14x14mm, Pitch 0.5mm, IPC Low Density)
3D model M4LV-TQFP100 (100-Pin Thin Quad Flat Pack (TQFP100))
pins: 1 GND (power), 2 TDI (in), 3 I/O8 B7 (io), 4 I/O9 B6 (io), 5 I/O10 B5 (io), 6 I/O11 B4 (io), 7 I/O12 B3 (io), 8 I/O13 B2 (io), 9 I/O14 B1 (io), 10 I/O15 B0 (io), 11 I0/CLK0 (in), 12 VCC (power), 13 GND (power), 14 I1/CLK1 (in), 15 I/O16 C0 (io), 16 I/O17 C1 (io), 17 I/O18 C2 (io), 18 I/O19 C3 (io), 19 I/O20 C4 (io), 20 I/O21 C5 (io), 21 I/O22 C6 (io), 22 I/O23 C7 (io), 23 TMS (in), 24 TCK (in), 25 GND (power), 26 GND (power), 27 GND (power), 28 I/O24 D7 (io), 29 I/O25 D6 (io), 30 I/O26 D5 (io), 31 I/O27 D4 (io), 32 I/O28 D3 (io), 33 I/O29 D2 (io), 34 I/O30 D1 (io), 35 I/O31 D0 (io), 36 I2 (in), 37 VCC (power), 38 GND (power), 39 GND (power), 40 VCC (power), 41 I/O32 E0 (io), 42 I/O33 E1 (io), 43 I/O34 E2 (io), 44 I/O35 E3 (io), 45 I/O36 E4 (io), 46 I/O37 E5 (io), 47 I/O38 E6 (io), 48 I/O39 E7 (io), 49 GND (power), 50 GND (power), 51 GND (power), 52 ENABLE (in), 53 I/O40 F7 (io), 54 I/O41 F6 (io), 55 I/O42 F5 (io), 56 I/O43 F4 (io), 57 I/O44 F3 (io), 58 I/O45 F2 (io), 59 I/O46 F1 (io), 60 I/O47 F0 (io), 61 I3/CLK2 (in), 62 VCC (power), 63 GND (power), 64 I4/CLK3 (in), 65 I/O48 G0 (io), 66 I/O49 G1 (io), 67 I/O50 G2 (io), 68 I/O51 G3 (io), 69 I/O52 G4 (io), 70 I/O53 G5 (io), 71 I/O54 G6 (io), 72 I/O55 G7 (io), 73 TRST (in), 74 TDO (out), 75 GND (power), 76 GND (power), 77 GND (power), 78 I/O56 H7 (io), 79 I/O57 H6 (io), 80 I/O58 H5 (io), 81 I/O59 H4 (io), 82 I/O60 H3 (io), 83 I/O61 H2 (io), 84 I/O62 H1 (io), 85 I/O63 H0 (io), 86 I5 (in), 87 VCC (power), 88 GND (power), 89 GND (power), 90 VCC (power), 91 I/O0 A0 (io), 92 I/O1 A1 (io), 93 I/O2 A2 (io), 94 I/O3 A3 (io), 95 I/O4 A4 (io), 96 I/O5 A5 (io), 97 I/O6 A6 (io), 98 I/O7 A7 (io), 99 GND (power), 100 GND (power)

## M4LV-128/64-12VI
designator U?
High-Performance EE CMOS In-System Programmable Logic
footprint TQFP100_N (Thin QFP, 100-Leads, Body 14x14mm, Pitch 0.5mm, IPC Medium Density)
footprint TQFP100_L (Thin QFP, 100-Leads, Body 14x14mm, Pitch 0.5mm, IPC High Density)
footprint TQFP100_M (Thin QFP, 100-Leads, Body 14x14mm, Pitch 0.5mm, IPC Low Density)
3D model M4LV-TQFP100 (100-Pin Thin Quad Flat Pack (TQFP100))
pins: 1 GND (power), 2 TDI (in), 3 I/O8 B7 (io), 4 I/O9 B6 (io), 5 I/O10 B5 (io), 6 I/O11 B4 (io), 7 I/O12 B3 (io), 8 I/O13 B2 (io), 9 I/O14 B1 (io), 10 I/O15 B0 (io), 11 I0/CLK0 (in), 12 VCC (power), 13 GND (power), 14 I1/CLK1 (in), 15 I/O16 C0 (io), 16 I/O17 C1 (io), 17 I/O18 C2 (io), 18 I/O19 C3 (io), 19 I/O20 C4 (io), 20 I/O21 C5 (io), 21 I/O22 C6 (io), 22 I/O23 C7 (io), 23 TMS (in), 24 TCK (in), 25 GND (power), 26 GND (power), 27 GND (power), 28 I/O24 D7 (io), 29 I/O25 D6 (io), 30 I/O26 D5 (io), 31 I/O27 D4 (io), 32 I/O28 D3 (io), 33 I/O29 D2 (io), 34 I/O30 D1 (io), 35 I/O31 D0 (io), 36 I2 (in), 37 VCC (power), 38 GND (power), 39 GND (power), 40 VCC (power), 41 I/O32 E0 (io), 42 I/O33 E1 (io), 43 I/O34 E2 (io), 44 I/O35 E3 (io), 45 I/O36 E4 (io), 46 I/O37 E5 (io), 47 I/O38 E6 (io), 48 I/O39 E7 (io), 49 GND (power), 50 GND (power), 51 GND (power), 52 ENABLE (in), 53 I/O40 F7 (io), 54 I/O41 F6 (io), 55 I/O42 F5 (io), 56 I/O43 F4 (io), 57 I/O44 F3 (io), 58 I/O45 F2 (io), 59 I/O46 F1 (io), 60 I/O47 F0 (io), 61 I3/CLK2 (in), 62 VCC (power), 63 GND (power), 64 I4/CLK3 (in), 65 I/O48 G0 (io), 66 I/O49 G1 (io), 67 I/O50 G2 (io), 68 I/O51 G3 (io), 69 I/O52 G4 (io), 70 I/O53 G5 (io), 71 I/O54 G6 (io), 72 I/O55 G7 (io), 73 TRST (in), 74 TDO (out), 75 GND (power), 76 GND (power), 77 GND (power), 78 I/O56 H7 (io), 79 I/O57 H6 (io), 80 I/O58 H5 (io), 81 I/O59 H4 (io), 82 I/O60 H3 (io), 83 I/O61 H2 (io), 84 I/O62 H1 (io), 85 I/O63 H0 (io), 86 I5 (in), 87 VCC (power), 88 GND (power), 89 GND (power), 90 VCC (power), 91 I/O0 A0 (io), 92 I/O1 A1 (io), 93 I/O2 A2 (io), 94 I/O3 A3 (io), 95 I/O4 A4 (io), 96 I/O5 A5 (io), 97 I/O6 A6 (io), 98 I/O7 A7 (io), 99 GND (power), 100 GND (power)

## M4LV-128/64-12YC
designator U?
High-Performance EE CMOS In-System Programmable Logic
footprint PQFP100_N (QFP, 100-Leads, Body 20x14mm, Pitch 0.65mm, IPC Medium Density)
footprint PQFP100_L (QFP, 100-Leads, Body 20x14mm, Pitch 0.65mm, IPC High Density)
footprint PQFP100_M (QFP, 100-Leads, Body 20x14mm, Pitch 0.65mm, IPC Low Density)
3D model PQFP-100 (100-Pin Quad Flat Pack Rectangular 0.65 mm Pitch)
pins: 1 GND (power), 2 GND (power), 3 TDI (in), 4 I5 (in), 5 I/O8 B7 (io), 6 I/O9 B6 (io), 7 I/O10 B5 (io), 8 I/O11 B4 (io), 9 I/O12 B3 (io), 10 I/O13 B2 (io), 11 I/O14 B1 (io), 12 I/O15 B0 (io), 13 I0/CLK0 (in), 14 VCC (power), 15 VCC (power), 16 GND (power), 17 GND (power), 18 I1/CLK1 (in), 19 I/O16 C0 (io), 20 I/O17 C1 (io), 21 I/O18 C2 (io), 22 I/O19 C3 (io), 23 I/O20 C4 (io), 24 I/O21 C5 (io), 25 I/O22 C6 (io), 26 I/O23 C7 (io), 27 TMS (in), 28 TCK (in), 29 GND (power), 30 GND (power), 31 I/O24 D7 (io), 32 I/O25 D6 (io), 33 I/O26 D5 (io), 34 I/O27 D4 (io), 35 I/O28 D3 (io), 36 I/O29 D2 (io), 37 I/O30 D1 (io), 38 I/O31 D0 (io), 39 VCC (power), 40 GND (power), 41 GND (power), 42 VCC (power), 43 I/O32 E0 (io), 44 I/O33 E1 (io), 45 I/O34 E2 (io), 46 I/O35 E3 (io), 47 I/O36 E4 (io), 48 I/O37 E5 (io), 49 I/O38 E6 (io), 50 I/O39 E7 (io), 51 GND (power), 52 GND (power), 53 ENABLE (in), 54 I2 (in), 55 I/O40 F7 (io), 56 I/O41 F6 (io), 57 I/O42 F5 (io), 58 I/O43 F4 (io), 59 I/O44 F3 (io), 60 I/O45 F2 (io), 61 I/O46 F1 (io), 62 I/O47 F0 (io), 63 I3/CLK2 (in), 64 VCC (power), 65 VCC (power), 66 GND (power), 67 GND (power), 68 I4/CLK3 (in), 69 I/O48 G0 (io), 70 I/O49 G1 (io), 71 I/O50 G2 (io), 72 I/O51 G3 (io), 73 I/O52 G4 (io), 74 I/O53 G5 (io), 75 I/O54 G6 (io), 76 I/O55 G7 (io), 77 TRST (in), 78 TDO (out), 79 GND (power), 80 GND (power), 81 I/O56 H7 (io), 82 I/O57 H6 (io), 83 I/O58 H5 (io), 84 I/O59 H4 (io), 85 I/O60 H3 (io), 86 I/O61 H2 (io), 87 I/O62 H1 (io), 88 I/O63 H0 (io), 89 VCC (power), 90 GND (power), 91 GND (power), 92 VCC (power), 93 I/O0 A0 (io), 94 I/O1 A1 (io), 95 I/O2 A2 (io), 96 I/O3 A3 (io), 97 I/O4 A4 (io), 98 I/O5 A5 (io), 99 I/O6 A6 (io), 100 I/O7 A7 (io)

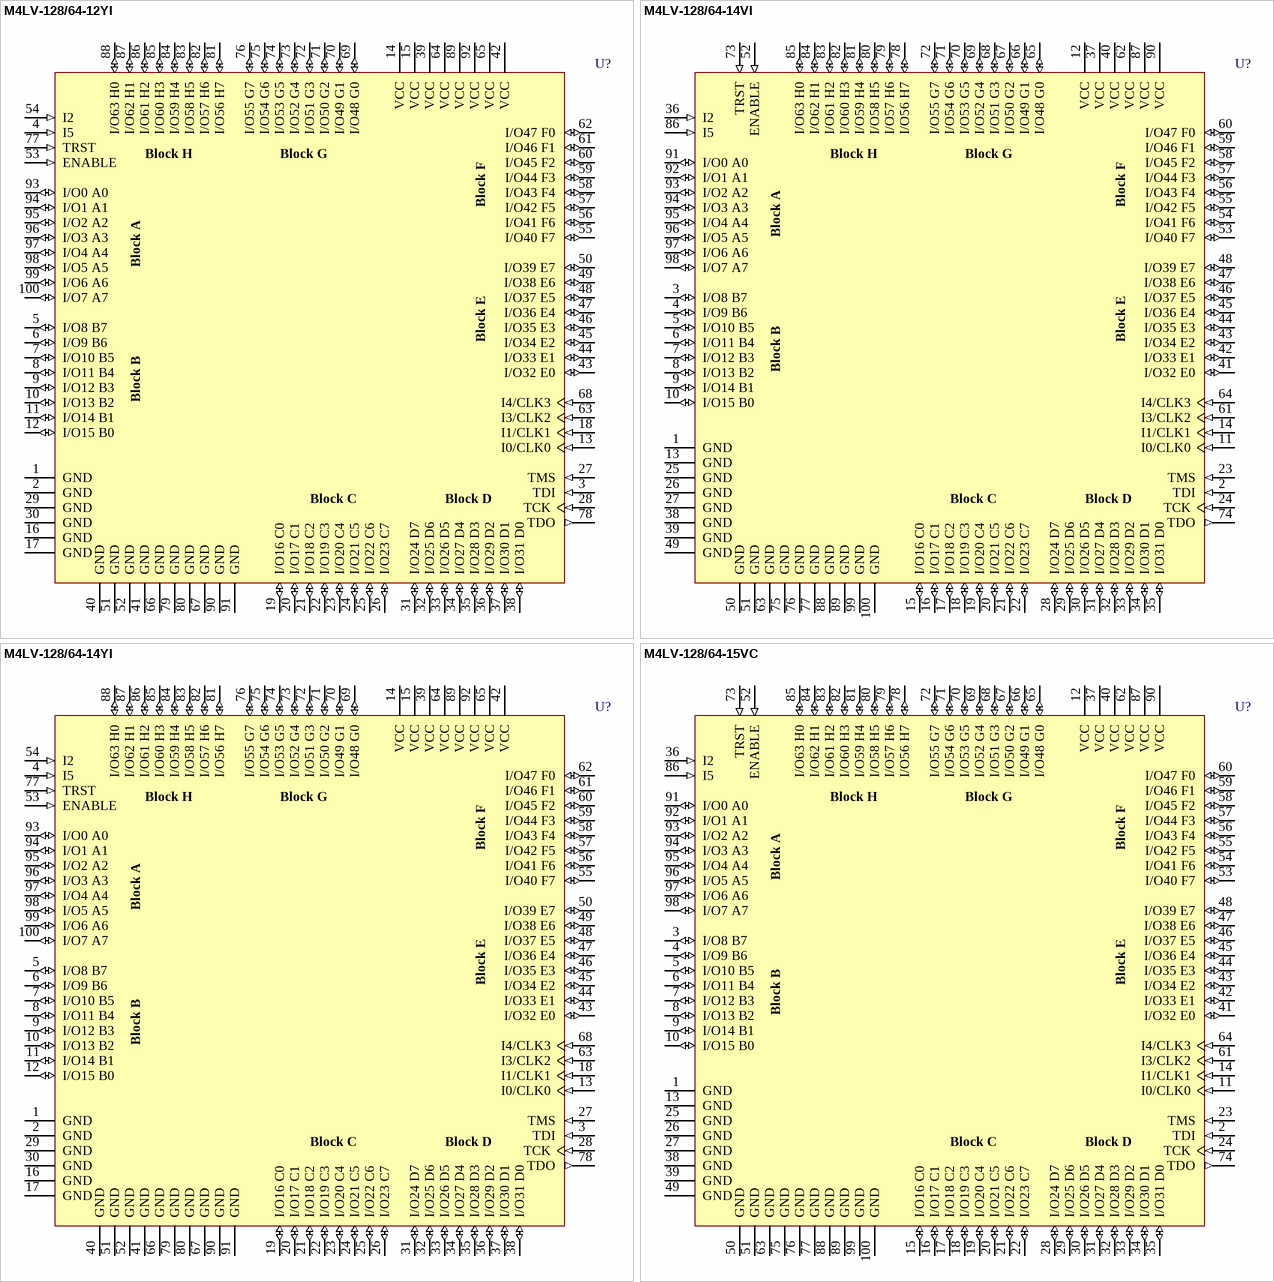
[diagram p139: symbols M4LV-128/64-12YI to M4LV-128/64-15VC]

## M4LV-128/64-12YI
designator U?
High-Performance EE CMOS In-System Programmable Logic
footprint PQFP100_N (QFP, 100-Leads, Body 20x14mm, Pitch 0.65mm, IPC Medium Density)
footprint PQFP100_L (QFP, 100-Leads, Body 20x14mm, Pitch 0.65mm, IPC High Density)
footprint PQFP100_M (QFP, 100-Leads, Body 20x14mm, Pitch 0.65mm, IPC Low Density)
3D model PQFP-100 (100-Pin Quad Flat Pack Rectangular 0.65 mm Pitch)
pins: 1 GND (power), 2 GND (power), 3 TDI (in), 4 I5 (in), 5 I/O8 B7 (io), 6 I/O9 B6 (io), 7 I/O10 B5 (io), 8 I/O11 B4 (io), 9 I/O12 B3 (io), 10 I/O13 B2 (io), 11 I/O14 B1 (io), 12 I/O15 B0 (io), 13 I0/CLK0 (in), 14 VCC (power), 15 VCC (power), 16 GND (power), 17 GND (power), 18 I1/CLK1 (in), 19 I/O16 C0 (io), 20 I/O17 C1 (io), 21 I/O18 C2 (io), 22 I/O19 C3 (io), 23 I/O20 C4 (io), 24 I/O21 C5 (io), 25 I/O22 C6 (io), 26 I/O23 C7 (io), 27 TMS (in), 28 TCK (in), 29 GND (power), 30 GND (power), 31 I/O24 D7 (io), 32 I/O25 D6 (io), 33 I/O26 D5 (io), 34 I/O27 D4 (io), 35 I/O28 D3 (io), 36 I/O29 D2 (io), 37 I/O30 D1 (io), 38 I/O31 D0 (io), 39 VCC (power), 40 GND (power), 41 GND (power), 42 VCC (power), 43 I/O32 E0 (io), 44 I/O33 E1 (io), 45 I/O34 E2 (io), 46 I/O35 E3 (io), 47 I/O36 E4 (io), 48 I/O37 E5 (io), 49 I/O38 E6 (io), 50 I/O39 E7 (io), 51 GND (power), 52 GND (power), 53 ENABLE (in), 54 I2 (in), 55 I/O40 F7 (io), 56 I/O41 F6 (io), 57 I/O42 F5 (io), 58 I/O43 F4 (io), 59 I/O44 F3 (io), 60 I/O45 F2 (io), 61 I/O46 F1 (io), 62 I/O47 F0 (io), 63 I3/CLK2 (in), 64 VCC (power), 65 VCC (power), 66 GND (power), 67 GND (power), 68 I4/CLK3 (in), 69 I/O48 G0 (io), 70 I/O49 G1 (io), 71 I/O50 G2 (io), 72 I/O51 G3 (io), 73 I/O52 G4 (io), 74 I/O53 G5 (io), 75 I/O54 G6 (io), 76 I/O55 G7 (io), 77 TRST (in), 78 TDO (out), 79 GND (power), 80 GND (power), 81 I/O56 H7 (io), 82 I/O57 H6 (io), 83 I/O58 H5 (io), 84 I/O59 H4 (io), 85 I/O60 H3 (io), 86 I/O61 H2 (io), 87 I/O62 H1 (io), 88 I/O63 H0 (io), 89 VCC (power), 90 GND (power), 91 GND (power), 92 VCC (power), 93 I/O0 A0 (io), 94 I/O1 A1 (io), 95 I/O2 A2 (io), 96 I/O3 A3 (io), 97 I/O4 A4 (io), 98 I/O5 A5 (io), 99 I/O6 A6 (io), 100 I/O7 A7 (io)

## M4LV-128/64-14VI
designator U?
High-Performance EE CMOS In-System Programmable Logic
footprint TQFP100_N (Thin QFP, 100-Leads, Body 14x14mm, Pitch 0.5mm, IPC Medium Density)
footprint TQFP100_L (Thin QFP, 100-Leads, Body 14x14mm, Pitch 0.5mm, IPC High Density)
footprint TQFP100_M (Thin QFP, 100-Leads, Body 14x14mm, Pitch 0.5mm, IPC Low Density)
3D model M4LV-TQFP100 (100-Pin Thin Quad Flat Pack (TQFP100))
pins: 1 GND (power), 2 TDI (in), 3 I/O8 B7 (io), 4 I/O9 B6 (io), 5 I/O10 B5 (io), 6 I/O11 B4 (io), 7 I/O12 B3 (io), 8 I/O13 B2 (io), 9 I/O14 B1 (io), 10 I/O15 B0 (io), 11 I0/CLK0 (in), 12 VCC (power), 13 GND (power), 14 I1/CLK1 (in), 15 I/O16 C0 (io), 16 I/O17 C1 (io), 17 I/O18 C2 (io), 18 I/O19 C3 (io), 19 I/O20 C4 (io), 20 I/O21 C5 (io), 21 I/O22 C6 (io), 22 I/O23 C7 (io), 23 TMS (in), 24 TCK (in), 25 GND (power), 26 GND (power), 27 GND (power), 28 I/O24 D7 (io), 29 I/O25 D6 (io), 30 I/O26 D5 (io), 31 I/O27 D4 (io), 32 I/O28 D3 (io), 33 I/O29 D2 (io), 34 I/O30 D1 (io), 35 I/O31 D0 (io), 36 I2 (in), 37 VCC (power), 38 GND (power), 39 GND (power), 40 VCC (power), 41 I/O32 E0 (io), 42 I/O33 E1 (io), 43 I/O34 E2 (io), 44 I/O35 E3 (io), 45 I/O36 E4 (io), 46 I/O37 E5 (io), 47 I/O38 E6 (io), 48 I/O39 E7 (io), 49 GND (power), 50 GND (power), 51 GND (power), 52 ENABLE (in), 53 I/O40 F7 (io), 54 I/O41 F6 (io), 55 I/O42 F5 (io), 56 I/O43 F4 (io), 57 I/O44 F3 (io), 58 I/O45 F2 (io), 59 I/O46 F1 (io), 60 I/O47 F0 (io), 61 I3/CLK2 (in), 62 VCC (power), 63 GND (power), 64 I4/CLK3 (in), 65 I/O48 G0 (io), 66 I/O49 G1 (io), 67 I/O50 G2 (io), 68 I/O51 G3 (io), 69 I/O52 G4 (io), 70 I/O53 G5 (io), 71 I/O54 G6 (io), 72 I/O55 G7 (io), 73 TRST (in), 74 TDO (out), 75 GND (power), 76 GND (power), 77 GND (power), 78 I/O56 H7 (io), 79 I/O57 H6 (io), 80 I/O58 H5 (io), 81 I/O59 H4 (io), 82 I/O60 H3 (io), 83 I/O61 H2 (io), 84 I/O62 H1 (io), 85 I/O63 H0 (io), 86 I5 (in), 87 VCC (power), 88 GND (power), 89 GND (power), 90 VCC (power), 91 I/O0 A0 (io), 92 I/O1 A1 (io), 93 I/O2 A2 (io), 94 I/O3 A3 (io), 95 I/O4 A4 (io), 96 I/O5 A5 (io), 97 I/O6 A6 (io), 98 I/O7 A7 (io), 99 GND (power), 100 GND (power)

## M4LV-128/64-14YI
designator U?
High-Performance EE CMOS In-System Programmable Logic
footprint PQFP100_N (QFP, 100-Leads, Body 20x14mm, Pitch 0.65mm, IPC Medium Density)
footprint PQFP100_L (QFP, 100-Leads, Body 20x14mm, Pitch 0.65mm, IPC High Density)
footprint PQFP100_M (QFP, 100-Leads, Body 20x14mm, Pitch 0.65mm, IPC Low Density)
3D model PQFP-100 (100-Pin Quad Flat Pack Rectangular 0.65 mm Pitch)
pins: 1 GND (power), 2 GND (power), 3 TDI (in), 4 I5 (in), 5 I/O8 B7 (io), 6 I/O9 B6 (io), 7 I/O10 B5 (io), 8 I/O11 B4 (io), 9 I/O12 B3 (io), 10 I/O13 B2 (io), 11 I/O14 B1 (io), 12 I/O15 B0 (io), 13 I0/CLK0 (in), 14 VCC (power), 15 VCC (power), 16 GND (power), 17 GND (power), 18 I1/CLK1 (in), 19 I/O16 C0 (io), 20 I/O17 C1 (io), 21 I/O18 C2 (io), 22 I/O19 C3 (io), 23 I/O20 C4 (io), 24 I/O21 C5 (io), 25 I/O22 C6 (io), 26 I/O23 C7 (io), 27 TMS (in), 28 TCK (in), 29 GND (power), 30 GND (power), 31 I/O24 D7 (io), 32 I/O25 D6 (io), 33 I/O26 D5 (io), 34 I/O27 D4 (io), 35 I/O28 D3 (io), 36 I/O29 D2 (io), 37 I/O30 D1 (io), 38 I/O31 D0 (io), 39 VCC (power), 40 GND (power), 41 GND (power), 42 VCC (power), 43 I/O32 E0 (io), 44 I/O33 E1 (io), 45 I/O34 E2 (io), 46 I/O35 E3 (io), 47 I/O36 E4 (io), 48 I/O37 E5 (io), 49 I/O38 E6 (io), 50 I/O39 E7 (io), 51 GND (power), 52 GND (power), 53 ENABLE (in), 54 I2 (in), 55 I/O40 F7 (io), 56 I/O41 F6 (io), 57 I/O42 F5 (io), 58 I/O43 F4 (io), 59 I/O44 F3 (io), 60 I/O45 F2 (io), 61 I/O46 F1 (io), 62 I/O47 F0 (io), 63 I3/CLK2 (in), 64 VCC (power), 65 VCC (power), 66 GND (power), 67 GND (power), 68 I4/CLK3 (in), 69 I/O48 G0 (io), 70 I/O49 G1 (io), 71 I/O50 G2 (io), 72 I/O51 G3 (io), 73 I/O52 G4 (io), 74 I/O53 G5 (io), 75 I/O54 G6 (io), 76 I/O55 G7 (io), 77 TRST (in), 78 TDO (out), 79 GND (power), 80 GND (power), 81 I/O56 H7 (io), 82 I/O57 H6 (io), 83 I/O58 H5 (io), 84 I/O59 H4 (io), 85 I/O60 H3 (io), 86 I/O61 H2 (io), 87 I/O62 H1 (io), 88 I/O63 H0 (io), 89 VCC (power), 90 GND (power), 91 GND (power), 92 VCC (power), 93 I/O0 A0 (io), 94 I/O1 A1 (io), 95 I/O2 A2 (io), 96 I/O3 A3 (io), 97 I/O4 A4 (io), 98 I/O5 A5 (io), 99 I/O6 A6 (io), 100 I/O7 A7 (io)

## M4LV-128/64-15VC
designator U?
High-Performance EE CMOS In-System Programmable Logic
footprint TQFP100_N (Thin QFP, 100-Leads, Body 14x14mm, Pitch 0.5mm, IPC Medium Density)
footprint TQFP100_L (Thin QFP, 100-Leads, Body 14x14mm, Pitch 0.5mm, IPC High Density)
footprint TQFP100_M (Thin QFP, 100-Leads, Body 14x14mm, Pitch 0.5mm, IPC Low Density)
3D model M4LV-TQFP100 (100-Pin Thin Quad Flat Pack (TQFP100))
pins: 1 GND (power), 2 TDI (in), 3 I/O8 B7 (io), 4 I/O9 B6 (io), 5 I/O10 B5 (io), 6 I/O11 B4 (io), 7 I/O12 B3 (io), 8 I/O13 B2 (io), 9 I/O14 B1 (io), 10 I/O15 B0 (io), 11 I0/CLK0 (in), 12 VCC (power), 13 GND (power), 14 I1/CLK1 (in), 15 I/O16 C0 (io), 16 I/O17 C1 (io), 17 I/O18 C2 (io), 18 I/O19 C3 (io), 19 I/O20 C4 (io), 20 I/O21 C5 (io), 21 I/O22 C6 (io), 22 I/O23 C7 (io), 23 TMS (in), 24 TCK (in), 25 GND (power), 26 GND (power), 27 GND (power), 28 I/O24 D7 (io), 29 I/O25 D6 (io), 30 I/O26 D5 (io), 31 I/O27 D4 (io), 32 I/O28 D3 (io), 33 I/O29 D2 (io), 34 I/O30 D1 (io), 35 I/O31 D0 (io), 36 I2 (in), 37 VCC (power), 38 GND (power), 39 GND (power), 40 VCC (power), 41 I/O32 E0 (io), 42 I/O33 E1 (io), 43 I/O34 E2 (io), 44 I/O35 E3 (io), 45 I/O36 E4 (io), 46 I/O37 E5 (io), 47 I/O38 E6 (io), 48 I/O39 E7 (io), 49 GND (power), 50 GND (power), 51 GND (power), 52 ENABLE (in), 53 I/O40 F7 (io), 54 I/O41 F6 (io), 55 I/O42 F5 (io), 56 I/O43 F4 (io), 57 I/O44 F3 (io), 58 I/O45 F2 (io), 59 I/O46 F1 (io), 60 I/O47 F0 (io), 61 I3/CLK2 (in), 62 VCC (power), 63 GND (power), 64 I4/CLK3 (in), 65 I/O48 G0 (io), 66 I/O49 G1 (io), 67 I/O50 G2 (io), 68 I/O51 G3 (io), 69 I/O52 G4 (io), 70 I/O53 G5 (io), 71 I/O54 G6 (io), 72 I/O55 G7 (io), 73 TRST (in), 74 TDO (out), 75 GND (power), 76 GND (power), 77 GND (power), 78 I/O56 H7 (io), 79 I/O57 H6 (io), 80 I/O58 H5 (io), 81 I/O59 H4 (io), 82 I/O60 H3 (io), 83 I/O61 H2 (io), 84 I/O62 H1 (io), 85 I/O63 H0 (io), 86 I5 (in), 87 VCC (power), 88 GND (power), 89 GND (power), 90 VCC (power), 91 I/O0 A0 (io), 92 I/O1 A1 (io), 93 I/O2 A2 (io), 94 I/O3 A3 (io), 95 I/O4 A4 (io), 96 I/O5 A5 (io), 97 I/O6 A6 (io), 98 I/O7 A7 (io), 99 GND (power), 100 GND (power)

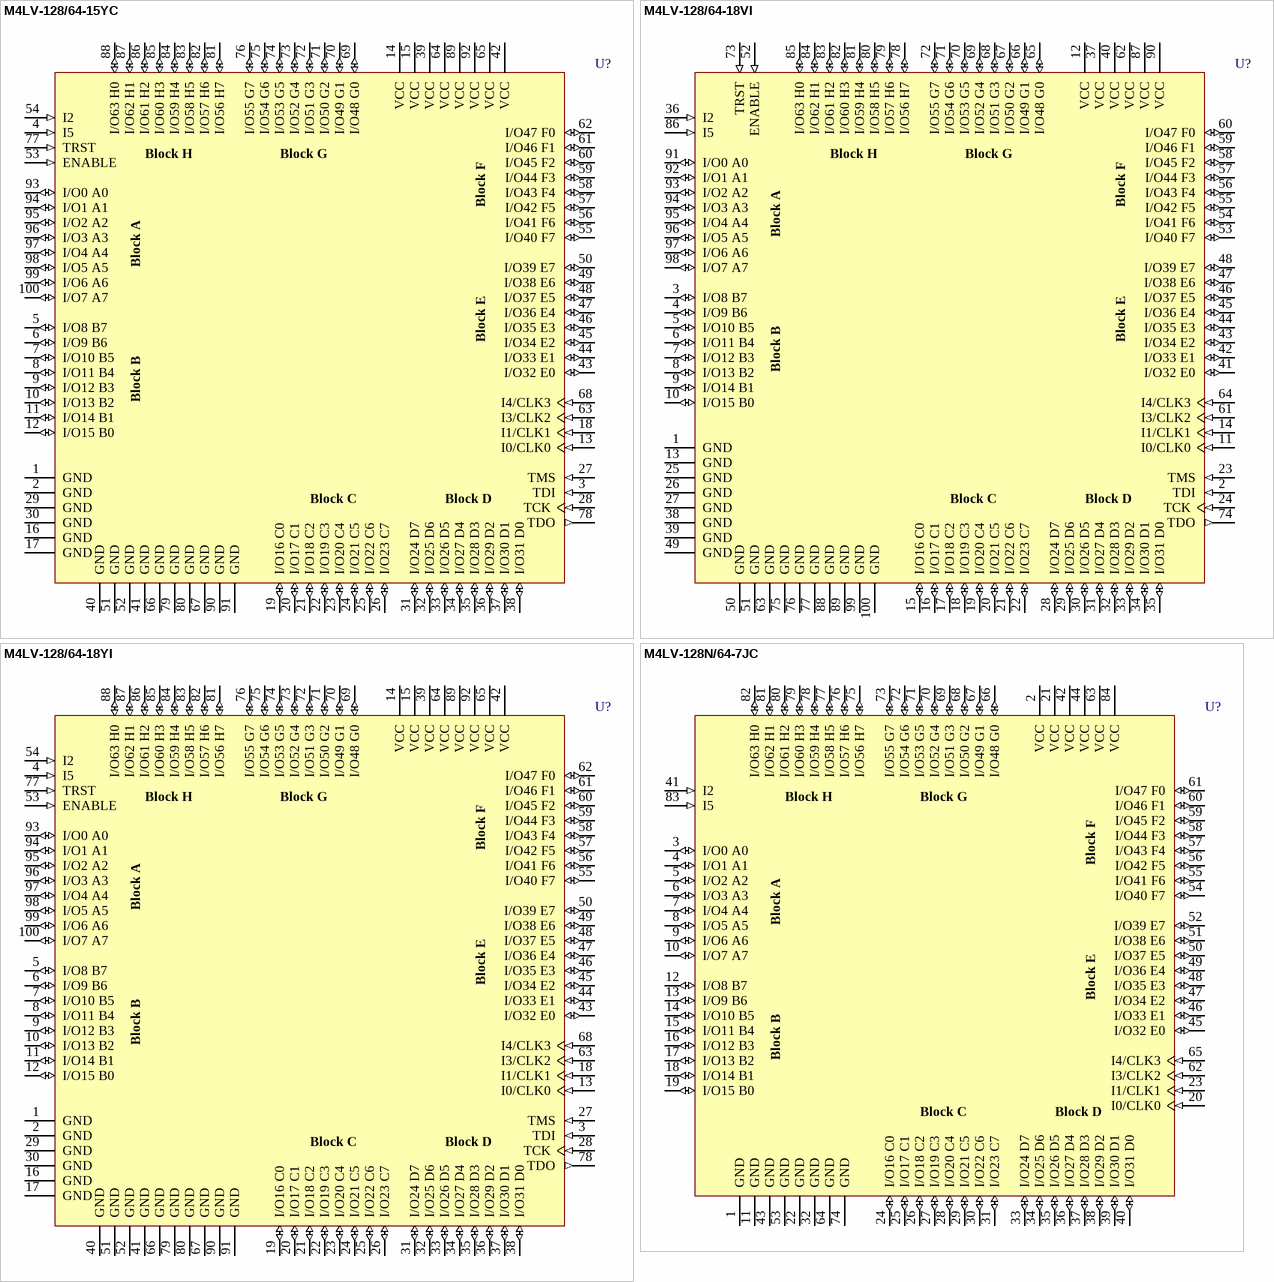
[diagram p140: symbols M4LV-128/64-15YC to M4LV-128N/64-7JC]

## M4LV-128/64-15YC
designator U?
High-Performance EE CMOS In-System Programmable Logic
footprint PQFP100_N (QFP, 100-Leads, Body 20x14mm, Pitch 0.65mm, IPC Medium Density)
footprint PQFP100_L (QFP, 100-Leads, Body 20x14mm, Pitch 0.65mm, IPC High Density)
footprint PQFP100_M (QFP, 100-Leads, Body 20x14mm, Pitch 0.65mm, IPC Low Density)
3D model PQFP-100 (100-Pin Quad Flat Pack Rectangular 0.65 mm Pitch)
pins: 1 GND (power), 2 GND (power), 3 TDI (in), 4 I5 (in), 5 I/O8 B7 (io), 6 I/O9 B6 (io), 7 I/O10 B5 (io), 8 I/O11 B4 (io), 9 I/O12 B3 (io), 10 I/O13 B2 (io), 11 I/O14 B1 (io), 12 I/O15 B0 (io), 13 I0/CLK0 (in), 14 VCC (power), 15 VCC (power), 16 GND (power), 17 GND (power), 18 I1/CLK1 (in), 19 I/O16 C0 (io), 20 I/O17 C1 (io), 21 I/O18 C2 (io), 22 I/O19 C3 (io), 23 I/O20 C4 (io), 24 I/O21 C5 (io), 25 I/O22 C6 (io), 26 I/O23 C7 (io), 27 TMS (in), 28 TCK (in), 29 GND (power), 30 GND (power), 31 I/O24 D7 (io), 32 I/O25 D6 (io), 33 I/O26 D5 (io), 34 I/O27 D4 (io), 35 I/O28 D3 (io), 36 I/O29 D2 (io), 37 I/O30 D1 (io), 38 I/O31 D0 (io), 39 VCC (power), 40 GND (power), 41 GND (power), 42 VCC (power), 43 I/O32 E0 (io), 44 I/O33 E1 (io), 45 I/O34 E2 (io), 46 I/O35 E3 (io), 47 I/O36 E4 (io), 48 I/O37 E5 (io), 49 I/O38 E6 (io), 50 I/O39 E7 (io), 51 GND (power), 52 GND (power), 53 ENABLE (in), 54 I2 (in), 55 I/O40 F7 (io), 56 I/O41 F6 (io), 57 I/O42 F5 (io), 58 I/O43 F4 (io), 59 I/O44 F3 (io), 60 I/O45 F2 (io), 61 I/O46 F1 (io), 62 I/O47 F0 (io), 63 I3/CLK2 (in), 64 VCC (power), 65 VCC (power), 66 GND (power), 67 GND (power), 68 I4/CLK3 (in), 69 I/O48 G0 (io), 70 I/O49 G1 (io), 71 I/O50 G2 (io), 72 I/O51 G3 (io), 73 I/O52 G4 (io), 74 I/O53 G5 (io), 75 I/O54 G6 (io), 76 I/O55 G7 (io), 77 TRST (in), 78 TDO (out), 79 GND (power), 80 GND (power), 81 I/O56 H7 (io), 82 I/O57 H6 (io), 83 I/O58 H5 (io), 84 I/O59 H4 (io), 85 I/O60 H3 (io), 86 I/O61 H2 (io), 87 I/O62 H1 (io), 88 I/O63 H0 (io), 89 VCC (power), 90 GND (power), 91 GND (power), 92 VCC (power), 93 I/O0 A0 (io), 94 I/O1 A1 (io), 95 I/O2 A2 (io), 96 I/O3 A3 (io), 97 I/O4 A4 (io), 98 I/O5 A5 (io), 99 I/O6 A6 (io), 100 I/O7 A7 (io)

## M4LV-128/64-18VI
designator U?
High-Performance EE CMOS In-System Programmable Logic
footprint TQFP100_N (Thin QFP, 100-Leads, Body 14x14mm, Pitch 0.5mm, IPC Medium Density)
footprint TQFP100_L (Thin QFP, 100-Leads, Body 14x14mm, Pitch 0.5mm, IPC High Density)
footprint TQFP100_M (Thin QFP, 100-Leads, Body 14x14mm, Pitch 0.5mm, IPC Low Density)
3D model M4LV-TQFP100 (100-Pin Thin Quad Flat Pack (TQFP100))
pins: 1 GND (power), 2 TDI (in), 3 I/O8 B7 (io), 4 I/O9 B6 (io), 5 I/O10 B5 (io), 6 I/O11 B4 (io), 7 I/O12 B3 (io), 8 I/O13 B2 (io), 9 I/O14 B1 (io), 10 I/O15 B0 (io), 11 I0/CLK0 (in), 12 VCC (power), 13 GND (power), 14 I1/CLK1 (in), 15 I/O16 C0 (io), 16 I/O17 C1 (io), 17 I/O18 C2 (io), 18 I/O19 C3 (io), 19 I/O20 C4 (io), 20 I/O21 C5 (io), 21 I/O22 C6 (io), 22 I/O23 C7 (io), 23 TMS (in), 24 TCK (in), 25 GND (power), 26 GND (power), 27 GND (power), 28 I/O24 D7 (io), 29 I/O25 D6 (io), 30 I/O26 D5 (io), 31 I/O27 D4 (io), 32 I/O28 D3 (io), 33 I/O29 D2 (io), 34 I/O30 D1 (io), 35 I/O31 D0 (io), 36 I2 (in), 37 VCC (power), 38 GND (power), 39 GND (power), 40 VCC (power), 41 I/O32 E0 (io), 42 I/O33 E1 (io), 43 I/O34 E2 (io), 44 I/O35 E3 (io), 45 I/O36 E4 (io), 46 I/O37 E5 (io), 47 I/O38 E6 (io), 48 I/O39 E7 (io), 49 GND (power), 50 GND (power), 51 GND (power), 52 ENABLE (in), 53 I/O40 F7 (io), 54 I/O41 F6 (io), 55 I/O42 F5 (io), 56 I/O43 F4 (io), 57 I/O44 F3 (io), 58 I/O45 F2 (io), 59 I/O46 F1 (io), 60 I/O47 F0 (io), 61 I3/CLK2 (in), 62 VCC (power), 63 GND (power), 64 I4/CLK3 (in), 65 I/O48 G0 (io), 66 I/O49 G1 (io), 67 I/O50 G2 (io), 68 I/O51 G3 (io), 69 I/O52 G4 (io), 70 I/O53 G5 (io), 71 I/O54 G6 (io), 72 I/O55 G7 (io), 73 TRST (in), 74 TDO (out), 75 GND (power), 76 GND (power), 77 GND (power), 78 I/O56 H7 (io), 79 I/O57 H6 (io), 80 I/O58 H5 (io), 81 I/O59 H4 (io), 82 I/O60 H3 (io), 83 I/O61 H2 (io), 84 I/O62 H1 (io), 85 I/O63 H0 (io), 86 I5 (in), 87 VCC (power), 88 GND (power), 89 GND (power), 90 VCC (power), 91 I/O0 A0 (io), 92 I/O1 A1 (io), 93 I/O2 A2 (io), 94 I/O3 A3 (io), 95 I/O4 A4 (io), 96 I/O5 A5 (io), 97 I/O6 A6 (io), 98 I/O7 A7 (io), 99 GND (power), 100 GND (power)

## M4LV-128/64-18YI
designator U?
High-Performance EE CMOS In-System Programmable Logic
footprint PQFP100_N (QFP, 100-Leads, Body 20x14mm, Pitch 0.65mm, IPC Medium Density)
footprint PQFP100_L (QFP, 100-Leads, Body 20x14mm, Pitch 0.65mm, IPC High Density)
footprint PQFP100_M (QFP, 100-Leads, Body 20x14mm, Pitch 0.65mm, IPC Low Density)
3D model PQFP-100 (100-Pin Quad Flat Pack Rectangular 0.65 mm Pitch)
pins: 1 GND (power), 2 GND (power), 3 TDI (in), 4 I5 (in), 5 I/O8 B7 (io), 6 I/O9 B6 (io), 7 I/O10 B5 (io), 8 I/O11 B4 (io), 9 I/O12 B3 (io), 10 I/O13 B2 (io), 11 I/O14 B1 (io), 12 I/O15 B0 (io), 13 I0/CLK0 (in), 14 VCC (power), 15 VCC (power), 16 GND (power), 17 GND (power), 18 I1/CLK1 (in), 19 I/O16 C0 (io), 20 I/O17 C1 (io), 21 I/O18 C2 (io), 22 I/O19 C3 (io), 23 I/O20 C4 (io), 24 I/O21 C5 (io), 25 I/O22 C6 (io), 26 I/O23 C7 (io), 27 TMS (in), 28 TCK (in), 29 GND (power), 30 GND (power), 31 I/O24 D7 (io), 32 I/O25 D6 (io), 33 I/O26 D5 (io), 34 I/O27 D4 (io), 35 I/O28 D3 (io), 36 I/O29 D2 (io), 37 I/O30 D1 (io), 38 I/O31 D0 (io), 39 VCC (power), 40 GND (power), 41 GND (power), 42 VCC (power), 43 I/O32 E0 (io), 44 I/O33 E1 (io), 45 I/O34 E2 (io), 46 I/O35 E3 (io), 47 I/O36 E4 (io), 48 I/O37 E5 (io), 49 I/O38 E6 (io), 50 I/O39 E7 (io), 51 GND (power), 52 GND (power), 53 ENABLE (in), 54 I2 (in), 55 I/O40 F7 (io), 56 I/O41 F6 (io), 57 I/O42 F5 (io), 58 I/O43 F4 (io), 59 I/O44 F3 (io), 60 I/O45 F2 (io), 61 I/O46 F1 (io), 62 I/O47 F0 (io), 63 I3/CLK2 (in), 64 VCC (power), 65 VCC (power), 66 GND (power), 67 GND (power), 68 I4/CLK3 (in), 69 I/O48 G0 (io), 70 I/O49 G1 (io), 71 I/O50 G2 (io), 72 I/O51 G3 (io), 73 I/O52 G4 (io), 74 I/O53 G5 (io), 75 I/O54 G6 (io), 76 I/O55 G7 (io), 77 TRST (in), 78 TDO (out), 79 GND (power), 80 GND (power), 81 I/O56 H7 (io), 82 I/O57 H6 (io), 83 I/O58 H5 (io), 84 I/O59 H4 (io), 85 I/O60 H3 (io), 86 I/O61 H2 (io), 87 I/O62 H1 (io), 88 I/O63 H0 (io), 89 VCC (power), 90 GND (power), 91 GND (power), 92 VCC (power), 93 I/O0 A0 (io), 94 I/O1 A1 (io), 95 I/O2 A2 (io), 96 I/O3 A3 (io), 97 I/O4 A4 (io), 98 I/O5 A5 (io), 99 I/O6 A6 (io), 100 I/O7 A7 (io)

## M4LV-128N/64-7JC
designator U?
High-Performance EE CMOS In-System Programmable Logic
footprint PLCC84_N (Leaded Chip Carrier, 84-Leads, Body 29.3x29.3mm, Pitch 1.27mm, IPC Medium Density)
footprint PLCC84_L (Leaded Chip Carrier, 84-Leads, Body 29.3x29.3mm, Pitch 1.27mm, IPC High Density)
footprint PLCC84_M (Leaded Chip Carrier, 84-Leads, Body 29.3x29.3mm, Pitch 1.27mm, IPC Low Density)
3D model M4LV-PLCC84 (84-Pin Leaded Chip Carrier 1.27 mm Pitch)
pins: 1 GND (power), 2 VCC (power), 3 I/O0 A0 (io), 4 I/O1 A1 (io), 5 I/O2 A2 (io), 6 I/O3 A3 (io), 7 I/O4 A4 (io), 8 I/O5 A5 (io), 9 I/O6 A6 (io), 10 I/O7 A7 (io), 11 GND (power), 12 I/O8 B7 (io), 13 I/O9 B6 (io), 14 I/O10 B5 (io), 15 I/O11 B4 (io), 16 I/O12 B3 (io), 17 I/O13 B2 (io), 18 I/O14 B1 (io), 19 I/O15 B0 (io), 20 I0/CLK0 (in), 21 VCC (power), 22 GND (power), 23 I1/CLK1 (in), 24 I/O16 C0 (io), 25 I/O17 C1 (io), 26 I/O18 C2 (io), 27 I/O19 C3 (io), 28 I/O20 C4 (io), 29 I/O21 C5 (io), 30 I/O22 C6 (io), 31 I/O23 C7 (io), 32 GND (power), 33 I/O24 D7 (io), 34 I/O25 D6 (io), 35 I/O26 D5 (io), 36 I/O27 D4 (io), 37 I/O28 D3 (io), 38 I/O29 D2 (io), 39 I/O30 D1 (io), 40 I/O31 D0 (io), 41 I2 (in), 42 VCC (power), 43 GND (power), 44 VCC (power), 45 I/O32 E0 (io), 46 I/O33 E1 (io), 47 I/O34 E2 (io), 48 I/O35 E3 (io), 49 I/O36 E4 (io), 50 I/O37 E5 (io), 51 I/O38 E6 (io), 52 I/O39 E7 (io), 53 GND (power), 54 I/O40 F7 (io), 55 I/O41 F6 (io), 56 I/O42 F5 (io), 57 I/O43 F4 (io), 58 I/O44 F3 (io), 59 I/O45 F2 (io), 60 I/O46 F1 (io), 61 I/O47 F0 (io), 62 I3/CLK2 (in), 63 VCC (power), 64 GND (power), 65 I4/CLK3 (in), 66 I/O48 G0 (io), 67 I/O49 G1 (io), 68 I/O50 G2 (io), 69 I/O51 G3 (io), 70 I/O52 G4 (io), 71 I/O53 G5 (io), 72 I/O54 G6 (io), 73 I/O55 G7 (io), 74 GND (power), 75 I/O56 H7 (io), 76 I/O57 H6 (io), 77 I/O58 H5 (io), 78 I/O59 H4 (io), 79 I/O60 H3 (io), 80 I/O61 H2 (io), 81 I/O62 H1 (io), 82 I/O63 H0 (io), 83 I5 (in), 84 VCC (power)

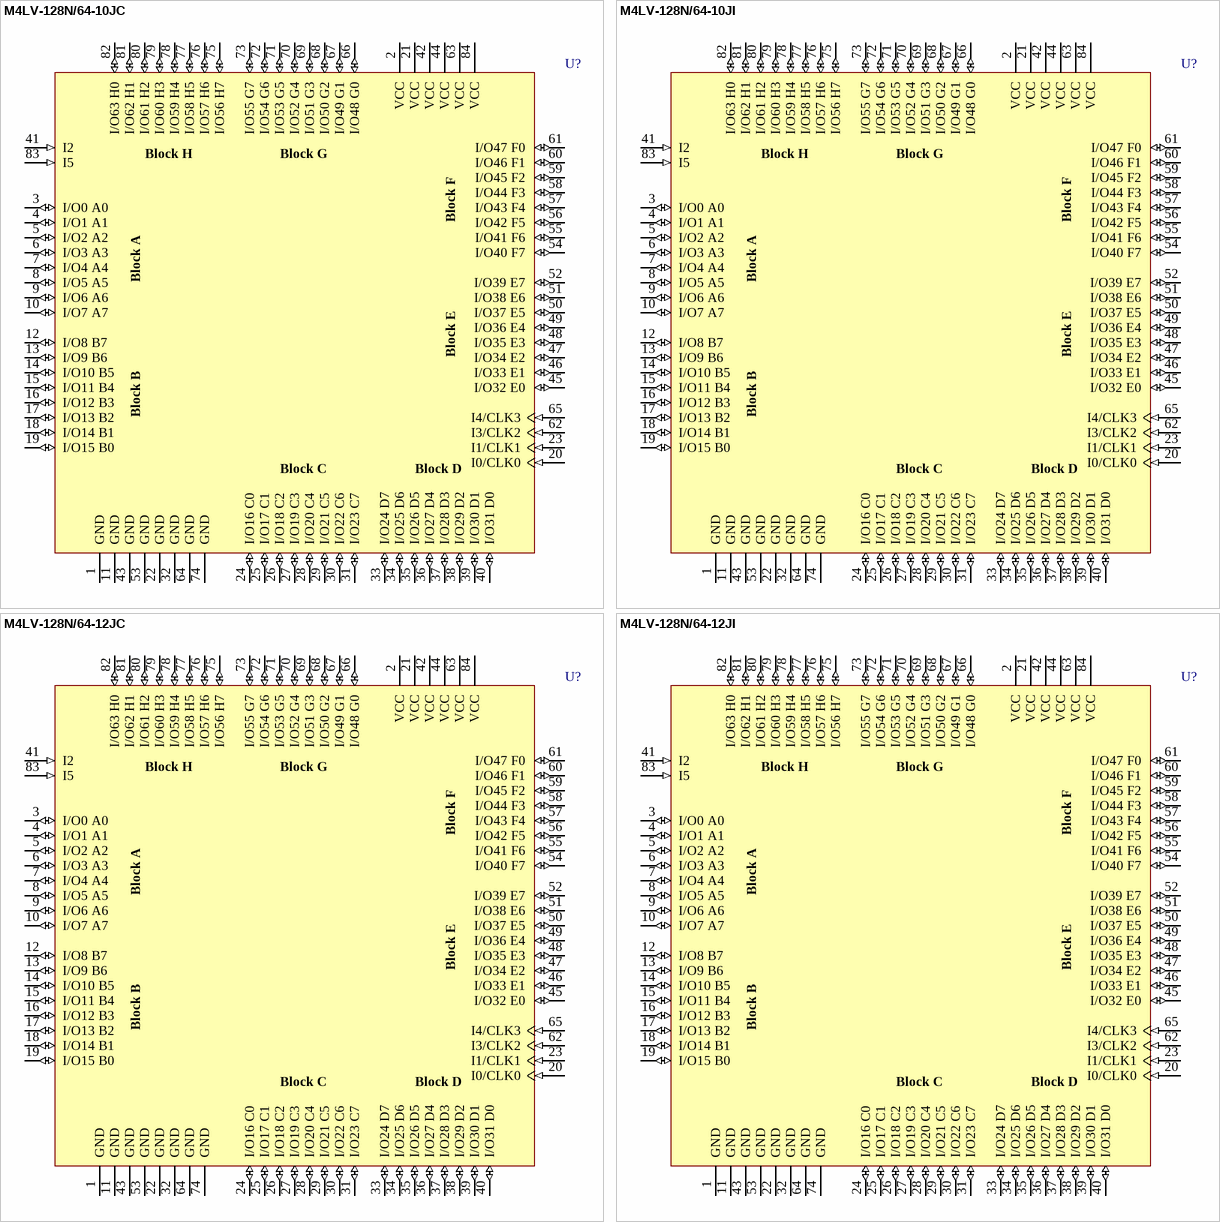
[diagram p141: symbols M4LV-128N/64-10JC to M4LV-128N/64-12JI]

## M4LV-128N/64-10JC
designator U?
High-Performance EE CMOS In-System Programmable Logic
footprint PLCC84_N (Leaded Chip Carrier, 84-Leads, Body 29.3x29.3mm, Pitch 1.27mm, IPC Medium Density)
footprint PLCC84_L (Leaded Chip Carrier, 84-Leads, Body 29.3x29.3mm, Pitch 1.27mm, IPC High Density)
footprint PLCC84_M (Leaded Chip Carrier, 84-Leads, Body 29.3x29.3mm, Pitch 1.27mm, IPC Low Density)
3D model M4LV-PLCC84 (84-Pin Leaded Chip Carrier 1.27 mm Pitch)
pins: 1 GND (power), 2 VCC (power), 3 I/O0 A0 (io), 4 I/O1 A1 (io), 5 I/O2 A2 (io), 6 I/O3 A3 (io), 7 I/O4 A4 (io), 8 I/O5 A5 (io), 9 I/O6 A6 (io), 10 I/O7 A7 (io), 11 GND (power), 12 I/O8 B7 (io), 13 I/O9 B6 (io), 14 I/O10 B5 (io), 15 I/O11 B4 (io), 16 I/O12 B3 (io), 17 I/O13 B2 (io), 18 I/O14 B1 (io), 19 I/O15 B0 (io), 20 I0/CLK0 (in), 21 VCC (power), 22 GND (power), 23 I1/CLK1 (in), 24 I/O16 C0 (io), 25 I/O17 C1 (io), 26 I/O18 C2 (io), 27 I/O19 C3 (io), 28 I/O20 C4 (io), 29 I/O21 C5 (io), 30 I/O22 C6 (io), 31 I/O23 C7 (io), 32 GND (power), 33 I/O24 D7 (io), 34 I/O25 D6 (io), 35 I/O26 D5 (io), 36 I/O27 D4 (io), 37 I/O28 D3 (io), 38 I/O29 D2 (io), 39 I/O30 D1 (io), 40 I/O31 D0 (io), 41 I2 (in), 42 VCC (power), 43 GND (power), 44 VCC (power), 45 I/O32 E0 (io), 46 I/O33 E1 (io), 47 I/O34 E2 (io), 48 I/O35 E3 (io), 49 I/O36 E4 (io), 50 I/O37 E5 (io), 51 I/O38 E6 (io), 52 I/O39 E7 (io), 53 GND (power), 54 I/O40 F7 (io), 55 I/O41 F6 (io), 56 I/O42 F5 (io), 57 I/O43 F4 (io), 58 I/O44 F3 (io), 59 I/O45 F2 (io), 60 I/O46 F1 (io), 61 I/O47 F0 (io), 62 I3/CLK2 (in), 63 VCC (power), 64 GND (power), 65 I4/CLK3 (in), 66 I/O48 G0 (io), 67 I/O49 G1 (io), 68 I/O50 G2 (io), 69 I/O51 G3 (io), 70 I/O52 G4 (io), 71 I/O53 G5 (io), 72 I/O54 G6 (io), 73 I/O55 G7 (io), 74 GND (power), 75 I/O56 H7 (io), 76 I/O57 H6 (io), 77 I/O58 H5 (io), 78 I/O59 H4 (io), 79 I/O60 H3 (io), 80 I/O61 H2 (io), 81 I/O62 H1 (io), 82 I/O63 H0 (io), 83 I5 (in), 84 VCC (power)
